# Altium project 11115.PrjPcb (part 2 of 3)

## Sheet 11115-4-USB-C Downstream 1-2.SchDoc
size Tabloid; CompanyName: Microchip Technology Inc.; Organization: Microchip Technology; Address1: 2355 West Chandler Blvd.; Address2: Chandler, AZ  85224; Address4: USA; SheetNumber: 4; SheetTotal: 6; SheetTitle: USB3.2 (Type-C) Downstream Ports 1 and 2
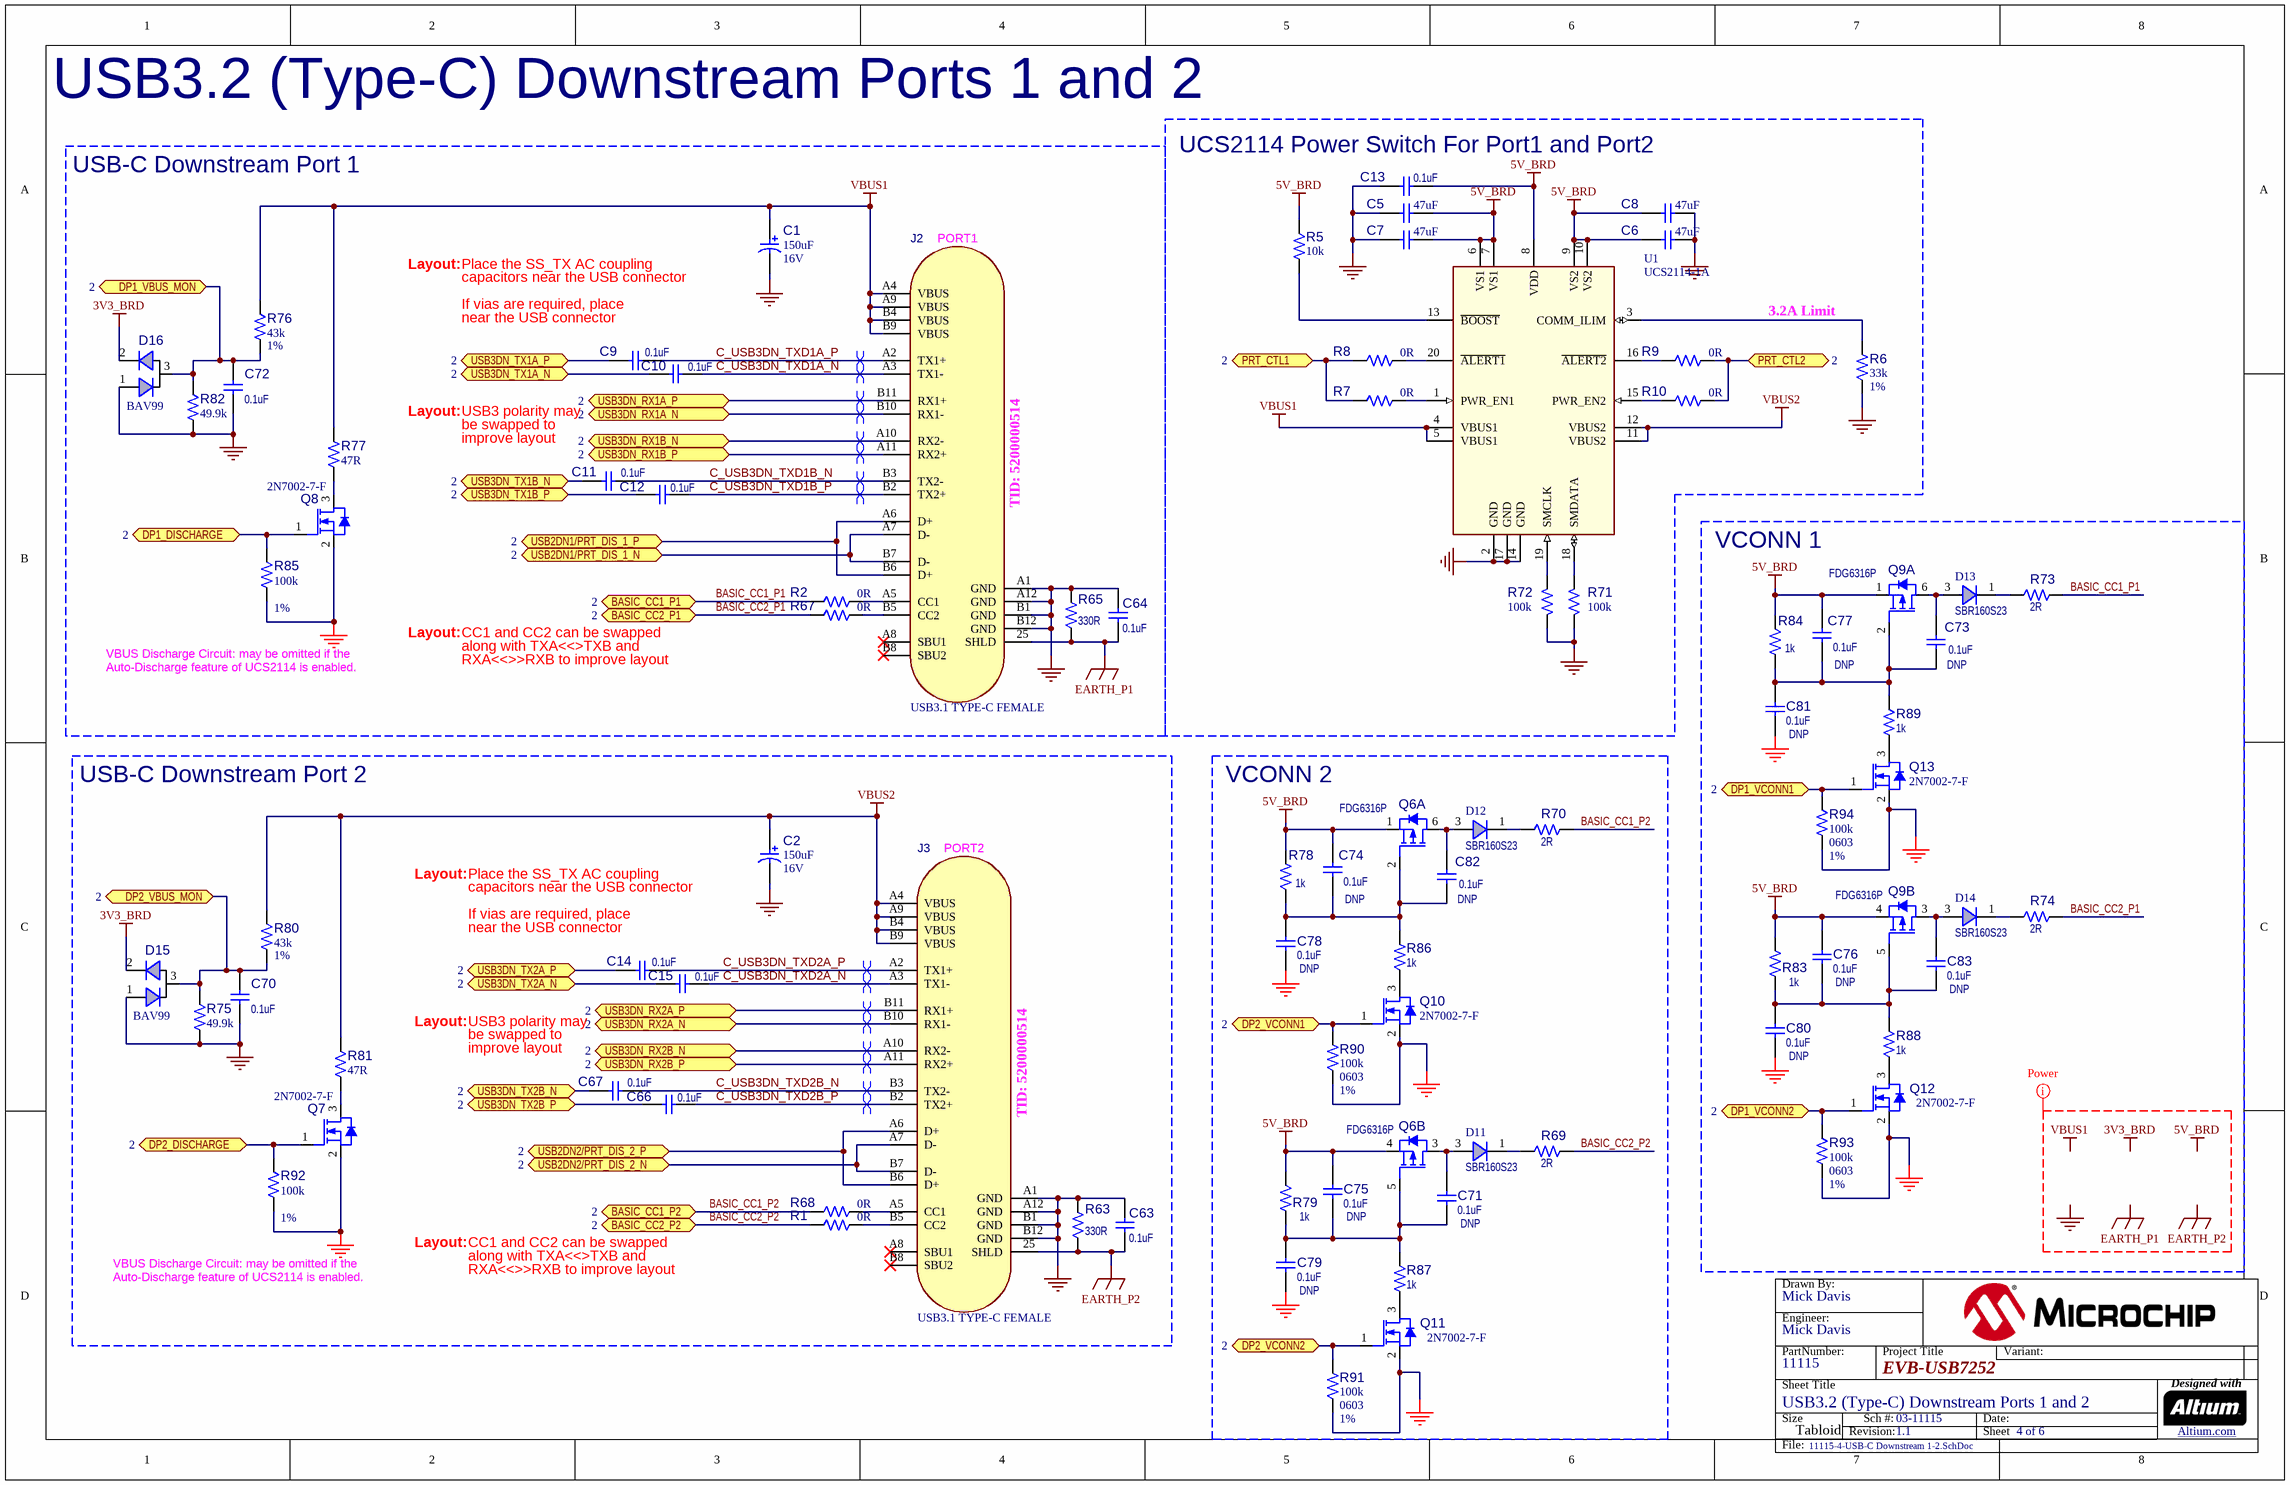
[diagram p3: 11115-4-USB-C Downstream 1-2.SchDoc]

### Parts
(Parts that share a designator on the sheet are numbered #1, #2 ... from top to bottom, then left to right.)
?#4  (no value)  (graphical)
C1  value 150uF  Voltage: 16V  [CAP_AL_D8]  (hidden comment: Capacitor POL)
C2  value 150uF  Voltage: 16V  [CAP_AL_D8]  (hidden comment: Capacitor POL)
C5  value 47uF  [CAP_C_0805]  (hidden comment: Capacitor NP)
C6  value 47uF  [CAP_C_0805]  (hidden comment: Capacitor NP)
C7  value 47uF  [CAP_C_0805]  (hidden comment: Capacitor NP)
C8  value 47uF  [CAP_C_0805]  (hidden comment: Capacitor NP)
C9  value 0.1uF  [CAP_C_0402]  (hidden comment: Capacitor NP)
C10  value 0.1uF  [CAP_C_0402]  (hidden comment: Capacitor NP)
C11  value 0.1uF  [CAP_C_0402]  (hidden comment: Capacitor NP)
C12  value 0.1uF  [CAP_C_0402]  (hidden comment: Capacitor NP)
C13  value 0.1uF  [CAP_C_0402]  (hidden comment: Capacitor NP)
C14  value 0.1uF  [CAP_C_0402]  (hidden comment: Capacitor NP)
C15  value 0.1uF  [CAP_C_0402]  (hidden comment: Capacitor NP)
C63  value 0.1uF  [CAP_C_0402]  (hidden comment: Capacitor NP)
C64  value 0.1uF  [CAP_C_0402]  (hidden comment: Capacitor NP)
C66  value 0.1uF  [CAP_C_0402]  (hidden comment: Capacitor NP)
C67  value 0.1uF  [CAP_C_0402]  (hidden comment: Capacitor NP)
C70  value 0.1uF  [CAP_C_0402]  (hidden comment: Capacitor NP)
C71  value 0.1uF  Populated: DNP  [CAP_C_0402]  (hidden comment: Capacitor NP)
C72  value 0.1uF  [CAP_C_0402]  (hidden comment: Capacitor NP)
C73  value 0.1uF  Populated: DNP  [CAP_C_0402]  (hidden comment: Capacitor NP)
C74  value 0.1uF  Populated: DNP  [CAP_C_0402]  (hidden comment: Capacitor NP)
C75  value 0.1uF  Populated: DNP  [CAP_C_0402]  (hidden comment: Capacitor NP)
C76  value 0.1uF  Populated: DNP  [CAP_C_0402]  (hidden comment: Capacitor NP)
C77  value 0.1uF  Populated: DNP  [CAP_C_0402]  (hidden comment: Capacitor NP)
C78  value 0.1uF  Populated: DNP  [CAP_C_0402]  (hidden comment: Capacitor NP)
C79  value 0.1uF  Populated: DNP  [CAP_C_0402]  (hidden comment: Capacitor NP)
C80  value 0.1uF  Populated: DNP  [CAP_C_0402]  (hidden comment: Capacitor NP)
C81  value 0.1uF  Populated: DNP  [CAP_C_0402]  (hidden comment: Capacitor NP)
C82  value 0.1uF  Populated: DNP  [CAP_C_0402]  (hidden comment: Capacitor NP)
C83  value 0.1uF  Populated: DNP  [CAP_C_0402]  (hidden comment: Capacitor NP)
D11  value SBR160S23  [SOT-23-3_REVERSED]  (hidden comment: Diode SBR160S23)
D12  value SBR160S23  [SOT-23-3_REVERSED]  (hidden comment: Diode SBR160S23)
D13  value SBR160S23  [SOT-23-3_REVERSED]  (hidden comment: Diode SBR160S23)
D14  value SBR160S23  [SOT-23-3_REVERSED]  (hidden comment: Diode SBR160S23)
D15  value BAV99  [SOT-23-3]  (hidden comment: Diode Dual AK)
D16  value BAV99  [SOT-23-3]  (hidden comment: Diode Dual AK)
J2  value USB3.1 TYPE-C FEMALE  [CON_USB3.1-C_RCPT_SMD_RA_ACP_12401610E4#2A]  (hidden comment: USBC_Receptacle_SMD_RA)
J3  value USB3.1 TYPE-C FEMALE  [CON_USB3.1-C_RCPT_SMD_RA_ACP_12401610E4#2A]  (hidden comment: USBC_Receptacle_SMD_RA)
Q6  value FDG6316P  [SC-88-6]  (hidden comment: Transistor MOS-P+P Dual SGDSGD)  (parts A,B of 2)
Q7  value 2N7002-7-F  [SOT-23-3]
Q8  value 2N7002-7-F  [SOT-23-3]
Q9  value FDG6316P  [SC-88-6]  (hidden comment: Transistor MOS-P+P Dual SGDSGD)  (parts A,B of 2)
Q10  value 2N7002-7-F  [SOT-23-3]
Q11  value 2N7002-7-F  [SOT-23-3]
Q12  value 2N7002-7-F  [SOT-23-3]
Q13  value 2N7002-7-F  [SOT-23-3]
R1  0R  [RES_C_0603]
R2  0R  [RES_C_0603]
R5  value 10k  [RES_C_0603]  (hidden comment: Resistor)
R6  value 33k  Tolerance: 1%  [RES_C_0603]  (hidden comment: Resistor)
R7  value 0R  [RES_C_0603]  (hidden comment: Resistor)
R8  value 0R  [RES_C_0603]  (hidden comment: Resistor)
R9  value 0R  [RES_C_0603]  (hidden comment: Resistor)
R10  value 0R  [RES_C_0603]  (hidden comment: Resistor)
R63  value 330R  [RES_C_0603]  (hidden comment: Resistor)
R65  value 330R  [RES_C_0603]  (hidden comment: Resistor)
R67  0R  [RES_C_0603]
R68  0R  [RES_C_0603]
R69  value 2R  [RES_C_0603]  (hidden comment: Resistor)
R70  value 2R  [RES_C_0603]  (hidden comment: Resistor)
R71  100k  [RES_C_0603]
R72  100k  [RES_C_0603]
R73  value 2R  [RES_C_0603]  (hidden comment: Resistor)
R74  value 2R  [RES_C_0603]  (hidden comment: Resistor)
R75  value 49.9k  [RES_C_0603]  (hidden comment: Resistor)
R76  value 43k  Tolerance: 1%  [RES_C_0603]  (hidden comment: Resistor)
R77  value 47R  [RES_C_0603]  (hidden comment: Resistor)
R78  value 1k  [RES_C_0603]  (hidden comment: Resistor)
R79  value 1k  [RES_C_0603]  (hidden comment: Resistor)
R80  value 43k  Tolerance: 1%  [RES_C_0603]  (hidden comment: Resistor)
R81  value 47R  [RES_C_0603]  (hidden comment: Resistor)
R82  value 49.9k  [RES_C_0603]  (hidden comment: Resistor)
R83  value 1k  [RES_C_0603]  (hidden comment: Resistor)
R84  value 1k  [RES_C_0603]  (hidden comment: Resistor)
R85  value 100k  Tolerance: 1%  [RES_C_0603]
R86  value 1k  [RES_C_0603]  (hidden comment: Resistor)
R87  value 1k  [RES_C_0603]  (hidden comment: Resistor)
R88  value 1k  [RES_C_0603]  (hidden comment: Resistor)
R89  value 1k  [RES_C_0603]  (hidden comment: Resistor)
R90  value 100k  Package: 0603  Tolerance: 1%  [RES_C_0603]
R91  value 100k  Package: 0603  Tolerance: 1%  [RES_C_0603]
R92  value 100k  Tolerance: 1%  [RES_C_0603]
R93  value 100k  Package: 0603  Tolerance: 1%  [RES_C_0603]
R94  value 100k  Package: 0603  Tolerance: 1%  [RES_C_0603]
U1  value UCS2114-1A  [QFN-20_3X3_P0.5_EP0_UCS2114]  (hidden comment: UCS2114 VQFN-20)

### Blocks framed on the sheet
USB-C Downstream Port 1: C1 C9-C12 C64 C72 D16 J2 Q8 R2 R65 R67 R76 R77 R82 R85
UCS2114 Power Switch For Port1 and Port2: C5-C8 C13 R5-R10 R71 R72 U1
VCONN 1: C73 C76 C77 C80 C81 C83 D13 D14 Q9 Q12 Q13 R73 R74 R83 R84 R88 R89 R93 R94
USB-C Downstream Port 2: C2 C14 C15 C63 C66 C67 C70 D15 J3 Q7 R1 R63 R68 R75 R80 R81 R92
VCONN 2: C71 C74 C75 C78 C79 C82 D11 D12 Q6 Q10 Q11 R69 R70 R78 R79 R86 R87 R90 R91

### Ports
BASIC_CC1_P1 (bidir, see 2), BASIC_CC1_P2 (bidir, see 2), BASIC_CC2_P1 (bidir, see 2), BASIC_CC2_P2 (bidir, see 2), DP1_DISCHARGE (bidir, see 2), DP1_VBUS_MON (bidir, see 2), DP1_VCONN1 (bidir, see 2), DP1_VCONN2 (bidir, see 2), DP2_DISCHARGE (bidir, see 2), DP2_VBUS_MON (bidir, see 2), DP2_VCONN1 (bidir, see 2), DP2_VCONN2 (bidir, see 2), PRT_CTL1 (bidir, see 2), PRT_CTL2 (bidir, see 2), USB2DN1/PRT_DIS_1_N (bidir, see 2), USB2DN1/PRT_DIS_1_P (bidir, see 2), USB2DN2/PRT_DIS_2_N (bidir, see 2), USB2DN2/PRT_DIS_2_P (bidir, see 2), USB3DN_RX1A_N (bidir, see 2), USB3DN_RX1A_P (bidir, see 2), USB3DN_RX1B_N (bidir, see 2), USB3DN_RX1B_P (bidir, see 2), USB3DN_RX2A_N (bidir, see 2), USB3DN_RX2A_P (bidir, see 2), USB3DN_RX2B_N (bidir, see 2), USB3DN_RX2B_P (bidir, see 2), USB3DN_TX1A_N (bidir, see 2), USB3DN_TX1A_P (bidir, see 2), USB3DN_TX1B_N (bidir, see 2), USB3DN_TX1B_P (bidir, see 2), USB3DN_TX2A_N (bidir, see 2), USB3DN_TX2A_P (bidir, see 2), USB3DN_TX2B_N (bidir, see 2), USB3DN_TX2B_P (bidir, see 2)

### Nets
3V3_BRD: D15.2(K) D16.2(K)
5V_BRD: C5.2 C6.1 C7.2 C8.1 C13.2 C74.2 C75.2 C76.2 C77.2 Q6.1(S1) Q6.4(S2) Q9.1(S1) Q9.4(S2) R5.1 R78.2 R79.2 R83.2 R84.2 U1.6(VS1) U1.7(VS1) U1.8(VDD) U1.9(VS2) U1.10(VS2)
EARTH_P1: C64.2 J2.25(SHLD) R65.1
EARTH_P2: C63.2 J3.25(SHLD) R63.1
GND: C1.2 C2.2 C5.1 C6.2 C7.1 C8.2 C13.1 C63.1 C64.1 C70.2 C72.2 C78.1 C79.1 C80.1 C81.1 D15.1(A) D16.1(A) J2.A1(GND) J2.A12(GND) J2.B1(GND) J2.B12(GND) J3.A1(GND) J3.A12(GND) J3.B1(GND) J3.B12(GND) Q7.2(S) Q8.2(S) Q10.2(S) Q11.2(S) Q12.2(S) Q13.2(S) R6.1 R63.2 R65.2 R71.2 R72.2 R75.1 R82.1 R85.1 R90.1 R91.1 R92.1 R93.1 R94.1 U1.2(GND) U1.14(GND) U1.17(GND)
VBUS1: C1.1 J2.A4(VBUS) J2.A9(VBUS) J2.B4(VBUS) J2.B9(VBUS) R76.2 R77.2 U1.4(VBUS1) U1.5(VBUS1)
VBUS2: C2.1 J3.A4(VBUS) J3.A9(VBUS) J3.B4(VBUS) J3.B9(VBUS) R80.2 R81.2 U1.11(VBUS2) U1.12(VBUS2)
BASIC_CC1_P1: R2.1 R73.2 ; port BASIC_CC1_P1
BASIC_CC1_P2: R68.1 R70.2 ; port BASIC_CC1_P2
BASIC_CC2_P1: R67.1 R74.2 ; port BASIC_CC2_P1
BASIC_CC2_P2: R1.1 R69.2 ; port BASIC_CC2_P2
C_USB3DN_TXD1A_N: C10.2 J2.A3(TX1-)
C_USB3DN_TXD1A_P: C9.2 J2.A2(TX1+)
C_USB3DN_TXD1B_N: C11.2 J2.B3(TX2-)
C_USB3DN_TXD1B_P: C12.2 J2.B2(TX2+)
C_USB3DN_TXD2A_N: C15.2 J3.A3(TX1-)
C_USB3DN_TXD2A_P: C14.2 J3.A2(TX1+)
C_USB3DN_TXD2B_N: C67.2 J3.B3(TX2-)
C_USB3DN_TXD2B_P: C66.2 J3.B2(TX2+)
DP1_DISCHARGE: Q8.1(G) R85.2 ; port DP1_DISCHARGE
DP1_VBUS_MON: C72.1 D16.3(KA) R76.1 R82.2 ; port DP1_VBUS_MON
DP1_VCONN1: Q13.1(G) R94.2 ; port DP1_VCONN1
DP1_VCONN2: Q12.1(G) R93.2 ; port DP1_VCONN2
DP2_DISCHARGE: Q7.1(G) R92.2 ; port DP2_DISCHARGE
DP2_VBUS_MON: C70.1 D15.3(KA) R75.2 R80.1 ; port DP2_VBUS_MON
DP2_VCONN1: Q10.1(G) R90.2 ; port DP2_VCONN1
DP2_VCONN2: Q11.1(G) R91.2 ; port DP2_VCONN2
PRT_CTL1: R7.1 R8.1 ; port PRT_CTL1
PRT_CTL2: R9.2 R10.2 ; port PRT_CTL2
USB2DN1/PRT_DIS_1_N: J2.A7(D-) J2.B7(D-) ; port USB2DN1/PRT_DIS_1_N
USB2DN1/PRT_DIS_1_P: J2.A6(D+) J2.B6(D+) ; port USB2DN1/PRT_DIS_1_P
USB2DN2/PRT_DIS_2_N: J3.A7(D-) J3.B7(D-) ; port USB2DN2/PRT_DIS_2_N
USB2DN2/PRT_DIS_2_P: J3.A6(D+) J3.B6(D+) ; port USB2DN2/PRT_DIS_2_P
USB3DN_RX1A_N: J2.B10(RX1-) ; port USB3DN_RX1A_N
USB3DN_RX1A_P: J2.B11(RX1+) ; port USB3DN_RX1A_P
USB3DN_RX1B_N: J2.A10(RX2-) ; port USB3DN_RX1B_N
USB3DN_RX1B_P: J2.A11(RX2+) ; port USB3DN_RX1B_P
USB3DN_RX2A_N: J3.B10(RX1-) ; port USB3DN_RX2A_N
USB3DN_RX2A_P: J3.B11(RX1+) ; port USB3DN_RX2A_P
USB3DN_RX2B_N: J3.A10(RX2-) ; port USB3DN_RX2B_N
USB3DN_RX2B_P: J3.A11(RX2+) ; port USB3DN_RX2B_P
USB3DN_TX1A_N: C10.1 ; port USB3DN_TX1A_N
USB3DN_TX1A_P: C9.1 ; port USB3DN_TX1A_P
USB3DN_TX1B_N: C11.1 ; port USB3DN_TX1B_N
USB3DN_TX1B_P: C12.1 ; port USB3DN_TX1B_P
USB3DN_TX2A_N: C15.1 ; port USB3DN_TX2A_N
USB3DN_TX2A_P: C14.1 ; port USB3DN_TX2A_P
USB3DN_TX2B_N: C67.1 ; port USB3DN_TX2B_N
USB3DN_TX2B_P: C66.1 ; port USB3DN_TX2B_P
NetC71_1: C71.1 C75.1 C79.2 Q6.5(G2) R79.1 R87.2
NetC71_2: C71.2 D11.3(A3) Q6.3(D2)
NetC73_1: C73.1 C77.1 C81.2 Q9.2(G1) R84.1 R89.2
NetC73_2: C73.2 D13.3(A3) Q9.6(D1)
NetC74_1: C74.1 C78.2 C82.1 Q6.2(G1) R78.1 R86.2
NetC76_1: C76.1 C80.2 C83.1 Q9.5(G2) R83.1 R88.2
NetC82_2: C82.2 D12.3(A3) Q6.6(D1)
NetC83_2: C83.2 D14.3(A3) Q9.3(D2)
NetD11_1: D11.1(K2) R69.1
NetD12_1: D12.1(K2) R70.1
NetD13_1: D13.1(K2) R73.1
NetD14_1: D14.1(K2) R74.1
NetJ2_A5: J2.A5(CC1) R2.2
NetJ2_B5: J2.B5(CC2) R67.2
NetJ3_A5: J3.A5(CC1) R68.2
NetJ3_B5: J3.B5(CC2) R1.2
NetQ7_3: Q7.3(D) R81.1
NetQ8_3: Q8.3(D) R77.1
NetQ10_3: Q10.3(D) R86.1
NetQ11_3: Q11.3(D) R87.1
NetQ12_3: Q12.3(D) R88.1
NetQ13_3: Q13.3(D) R89.1
NetR5_2: R5.2 U1.13(~{BOOST})
NetR6_2: R6.2 U1.3(COMM_ILIM)
NetR7_2: R7.2 U1.1(PWR_EN1)
NetR8_2: R8.2 U1.20(~{ALERT1})
NetR9_1: R9.1 U1.16(~{ALERT2})
NetR10_1: R10.1 U1.15(PWR_EN2)
NetR71_1: R71.1 U1.18(SMDATA)
NetR72_1: R72.1 U1.19(SMCLK)

Not connected (* = marked no-connect by the designer): J2 A8(SBU1)* B8(SBU2)*; J3 A8(SBU1)* B8(SBU2)*

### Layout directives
differential pair; net class USB3.: C_USB3DN_TXD1A_N, C_USB3DN_TXD1A_P, C_USB3DN_TXD1B_N, C_USB3DN_TXD1B_P, C_USB3DN_TXD2A_N, C_USB3DN_TXD2A_P, C_USB3DN_TXD2B_N, C_USB3DN_TXD2B_P, USB3DN_RX1A_N, USB3DN_RX1A_P, USB3DN_RX1B_N, USB3DN_RX1B_P, USB3DN_RX2A_N, USB3DN_RX2A_P, USB3DN_RX2B_N, USB3DN_RX2B_P
net class Power: 3V3_BRD, 5V_BRD, EARTH_P1, EARTH_P2, GND, VBUS1

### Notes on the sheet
- USB3.2 (Type-C) Downstream Ports 1 and 2
- Layout:
- Place the SS_TX AC coupling
- capacitors near the USB connector
- (near J2) PORT1
- If vias are required, place
- (near C9) near the USB connector
- (near R9) 3.2A Limit
- USB3 polarity may
- be swapped to
- (near C11) improve layout
- (near J2) TID: 5200000514
- VBUS Discharge Circuit: may be omitted if the
- Auto-Discharge feature of UCS2114 is enabled.
- CC1 and CC2 can be swapped
- along with TXA<<>TXB and
- RXA<<>>RXB to improve layout
- (near J3) PORT2
- (near C14) near the USB connector
- (near C67) improve layout
- (near J3) TID: 5200000514
- Labels drawn without touching a wire or pin: 3V3_BRD, 5V_BRD, EARTH_P1, EARTH_P2, GND, VBUS1

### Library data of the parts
?#4 = Title Block Tabloid
C1 C2 = CAP1298: Capacitor; Manufacturer 1: Panasonic Electronic Components; Manufacturer Part Number 1: EEE-FPC151XAP; Description_: CAP ALU 150uF 16V 20% SMD D8; Dev Tools Status: Production; Tolerance: 20%; ESR: 0.16R; Type: Aluminum; Owner: Stephen Humberd; Populated: YES
C5-C8 = CAP0646: Capacitor; Manufacturer 1: Taiyo Yuden; Manufacturer Part Number 1: JMK212BJ476MG-T; Description_: CAP CER 47uF 6.3V 20% X5R SMD 0805; Dev Tools Status: Production; Tolerance: 20%; Temperature Coeffcient: X5R; Type: Ceramic; Populated: Yes; Voltage: 6.3V
C9-C15 C63 C64 C66 C67 C70 C72 = CAP1337: Capacitor; Manufacturer 1: TDK Corporation; Manufacturer Part Number 1: CGA2B3X7R1V104K050BB; Voltage: 35V; Description_: CAP CER 0.1uF 35V 10% X7R SMD 0402; Dev Tools Status: Design; Tolerance: 10%; Temperature Coeffcient: X7R; Type: Ceramic; Owner: Sam Charles; Populated: YES
C71 C73-C83 = CAP1337: Capacitor; Manufacturer 1: TDK Corporation; Manufacturer Part Number 1: CGA2B3X7R1V104K050BB; Voltage: 35V; Description_: CAP CER 0.1uF 35V 10% X7R SMD 0402; Dev Tools Status: Design; Tolerance: 10%; Temperature Coeffcient: X7R; Type: Ceramic; Owner: Sam Charles
D11-D14 = DIODE1156: Manufacturer 1: Diodes Incorporated; Manufacturer Part Number 1: SBR160S23-7; Description_: DIO SBAR SBR160S23-7 SBR 530mV 900mA 60V SMD SOT23-3; Dev Tools Status: Production; Type: Super Barrier; Forward Current: 900mA; Reverse Current: 100µA @ 45V; Reverse Voltage: 60V; Owner: Sam Charles; Populated: YES
D15 D16 = DIODE0073: Manufacturer 1: Fairchild; Description_: DIO RECTARR BAV99 1.25V 200mA 70V SOT-23-3; Type: Rectifier Array; Forward Current: 200mA; Power: 350mW; Reverse Current: 2.5uA; Reverse Voltage: 70V; Populated: YES; Dev Tools Status: Production
J2 J3 = CON1809: Manufacturer 1: Amphenol Commercial Products; Manufacturer Part Number 1: 12401610E4#2A; Description_: CON USB3.1 TID TYPE-C Female SMD R/A; Dev Tools Status: Design; Owner: Jennifer Hancock; Current: 5A; Populated: YES
Q6 Q9 = TRA1232: Transistor MOS Dual P+P SGDSGD; Manufacturer 1: ON Semiconductor; Description_: TRANS FET DUAL P+P FDG6316P 12V 0.7A 0.270R 0.3R SC-88; Dev Tools Status: Design; Type: FET; Current: 300mA; Drain to Source Voltage: 12V; Gate to Source Voltage: 1.5V; Power: 0.3W; Owner: Sam Charles; Populated: YES
Q7 Q8 Q10-Q13 = TRA1102: Transistor MOS; Manufacturer 1: Diodes Inc; Description_: TRANS FET N-CH 2N7002-7-F 60V 170mA 370mW SOT-23-3; Dev Tools Status: Production; Type: FET; Current: 170mA; Drain to Source Voltage: 60V; Gate to Source Voltage: 20V; Power: 370mW; Owner: Adrian M (M91404); Populated: YES
R1 R2 R67 R68 = RSMT0001: Resistor; Manufacturer 1: NIC Components; Manufacturer Part Number 1: NRC06Z0TRF; Description_: RES TKF 0R 1/10W SMD 0603; Power: 1/10W; Populated: Yes
R5 = RSMT0625: Manufacturer 1: ROHM; Manufacturer Part Number 1: MCR03EZPFX1002; Tolerance: 1%; Description_: RES TKF 10k 1% 1/10W SMD 0603; Voltage: 75V; Temperature Coeffcient: 100ppm/C; Power: 1/10W; Populated: Yes; Dev Tools Status: Production
R6 = RES1169: Manufacturer 1: Panasonic; Manufacturer Part Number 1: ERJ-3EKF3302V; Description_: RES TKF 33k 1% 1/10W SMD 0603; Dev Tools Status: Production; Voltage: 75V; Temperature Coeffcient: 100ppm/C; Power: 1/10W; Owner: Bogdan P (M91398); Populated: Yes
R7-R10 = RSMT0001: Manufacturer 1: Panasonic; Manufacturer Part Number 1: ERJ-3GSY0R00V; Description_: RES TKF 0R 1/10W SMD 0603; Power: 1/10W; Populated: Yes; Dev Tools Status: Production
R63 R65 = RSMT0626: Manufacturer 1: Panasonic; Manufacturer Part Number 1: ERJ-3EKF3300V; Tolerance: 1%; Description_: RES TKF 330R 1% 1/10W SMD 0603; Dev Tools Status: Production; Voltage: 75V; Temperature Coeffcient: 100ppm/C; Power: 1/10W; Populated: Yes
R69 R70 R73 R74 = RES1566: Manufacturer 1: Vishay Dale; Manufacturer Part Number 1: CRCW06032R00FKEAHP; Tolerance: 1%; Description_: RES TKF 2R 1% 1/4W SMD 0603; Dev Tools Status: Production; Voltage: 75V; Temperature Coeffcient: 100ppm/C; Power: 1/10W; Owner: Tad Ahlvers; Populated: YES
R71 R72 = RSMT0215: Resistor; Manufacturer 1: Panasonic; Manufacturer Part Number 1: ERJ-3EKF1003V; Description_: RES TKF 100k 1% 1/10W SMD 0603; Voltage: 75V; Temperature Coeffcient: 100ppm/C; Power: 1/10W; Populated: Yes
R75 R82 = RSMT0383: Manufacturer 1: Panasonic; Manufacturer Part Number 1: ERJ-3EKF4992V; Tolerance: 1%; Description_: RES TKF 49.9k 1% 1/10W SMD 0603; Dev Tools Status: Production; Voltage: 75V; Temperature Coeffcient: 100ppm/C; Power: 1/10W; Populated: Yes
R76 R80 = RSMT0665: Manufacturer 1: Yageo; Manufacturer Part Number 1: 9C06031A4302FKHFT; Description_: RES TKF 43k 1% 1/10W SMD 0603; Dev Tools Status: Production; Voltage: 50V; Temperature Coeffcient: 100ppm/C; Power: 1/10W; Populated: Yes
R77 R81 = RSMT0703: Manufacturer 1: ROHM; Manufacturer Part Number 1: MCR03EZPFX47R0; Tolerance: 1%; Description_: RES TKF 47R 1% 1/10W SMD 0603; Dev Tools Status: Production; Voltage: 50V; Temperature Coeffcient: 100ppm/C; Power: 1/10W; Populated: Yes
R78 R79 R83 R84 R86-R89 = RSMT0138: Manufacturer 1: Panasonic; Manufacturer Part Number 1: ERJ-3EKF1001V; Tolerance: 1%; Description_: RES TKF 1k 1% 1/10W SMD 0603; Dev Tools Status: Production; Voltage: 75V; Temperature Coeffcient: 100ppm/C; Power: 1/10W; Populated: Yes
R85 R90-R94 = RSMT0215: Resistor; Manufacturer 1: Panasonic; Manufacturer Part Number 1: ERJ-3EKF1003V; Description_: RES TKF 100k 1% 1/10W SMD 0603; Voltage: 75V; Temperature Coeffcient: 100ppm/C; Power: 1/10W; Populated: Yes; Dev Tools Status: Production
U1 = MIC8861: UCS2114 Dual USB port power; Manufacturer 1: Microchip Technology; Manufacturer Part Number 1: UCS2114-1A-V/LX; Description_: MCHP INTERFACE USB Pwr Controller w/Auto Dischg UCS2114 QFN-20; Dev Tools Status: Design; Owner: Sam Charles; Populated: YES

## Sheet 11115-5-USB-A Downstream 3-4.SchDoc
size Tabloid; CompanyName: Microchip Technology Inc.; Organization: Microchip Technology; Address1: 2355 West Chandler Blvd.; Address2: Chandler, AZ  85224; Address4: USA; SheetNumber: 5; SheetTotal: 6; SheetTitle: USB (Type-A) Downstream Ports 3-4
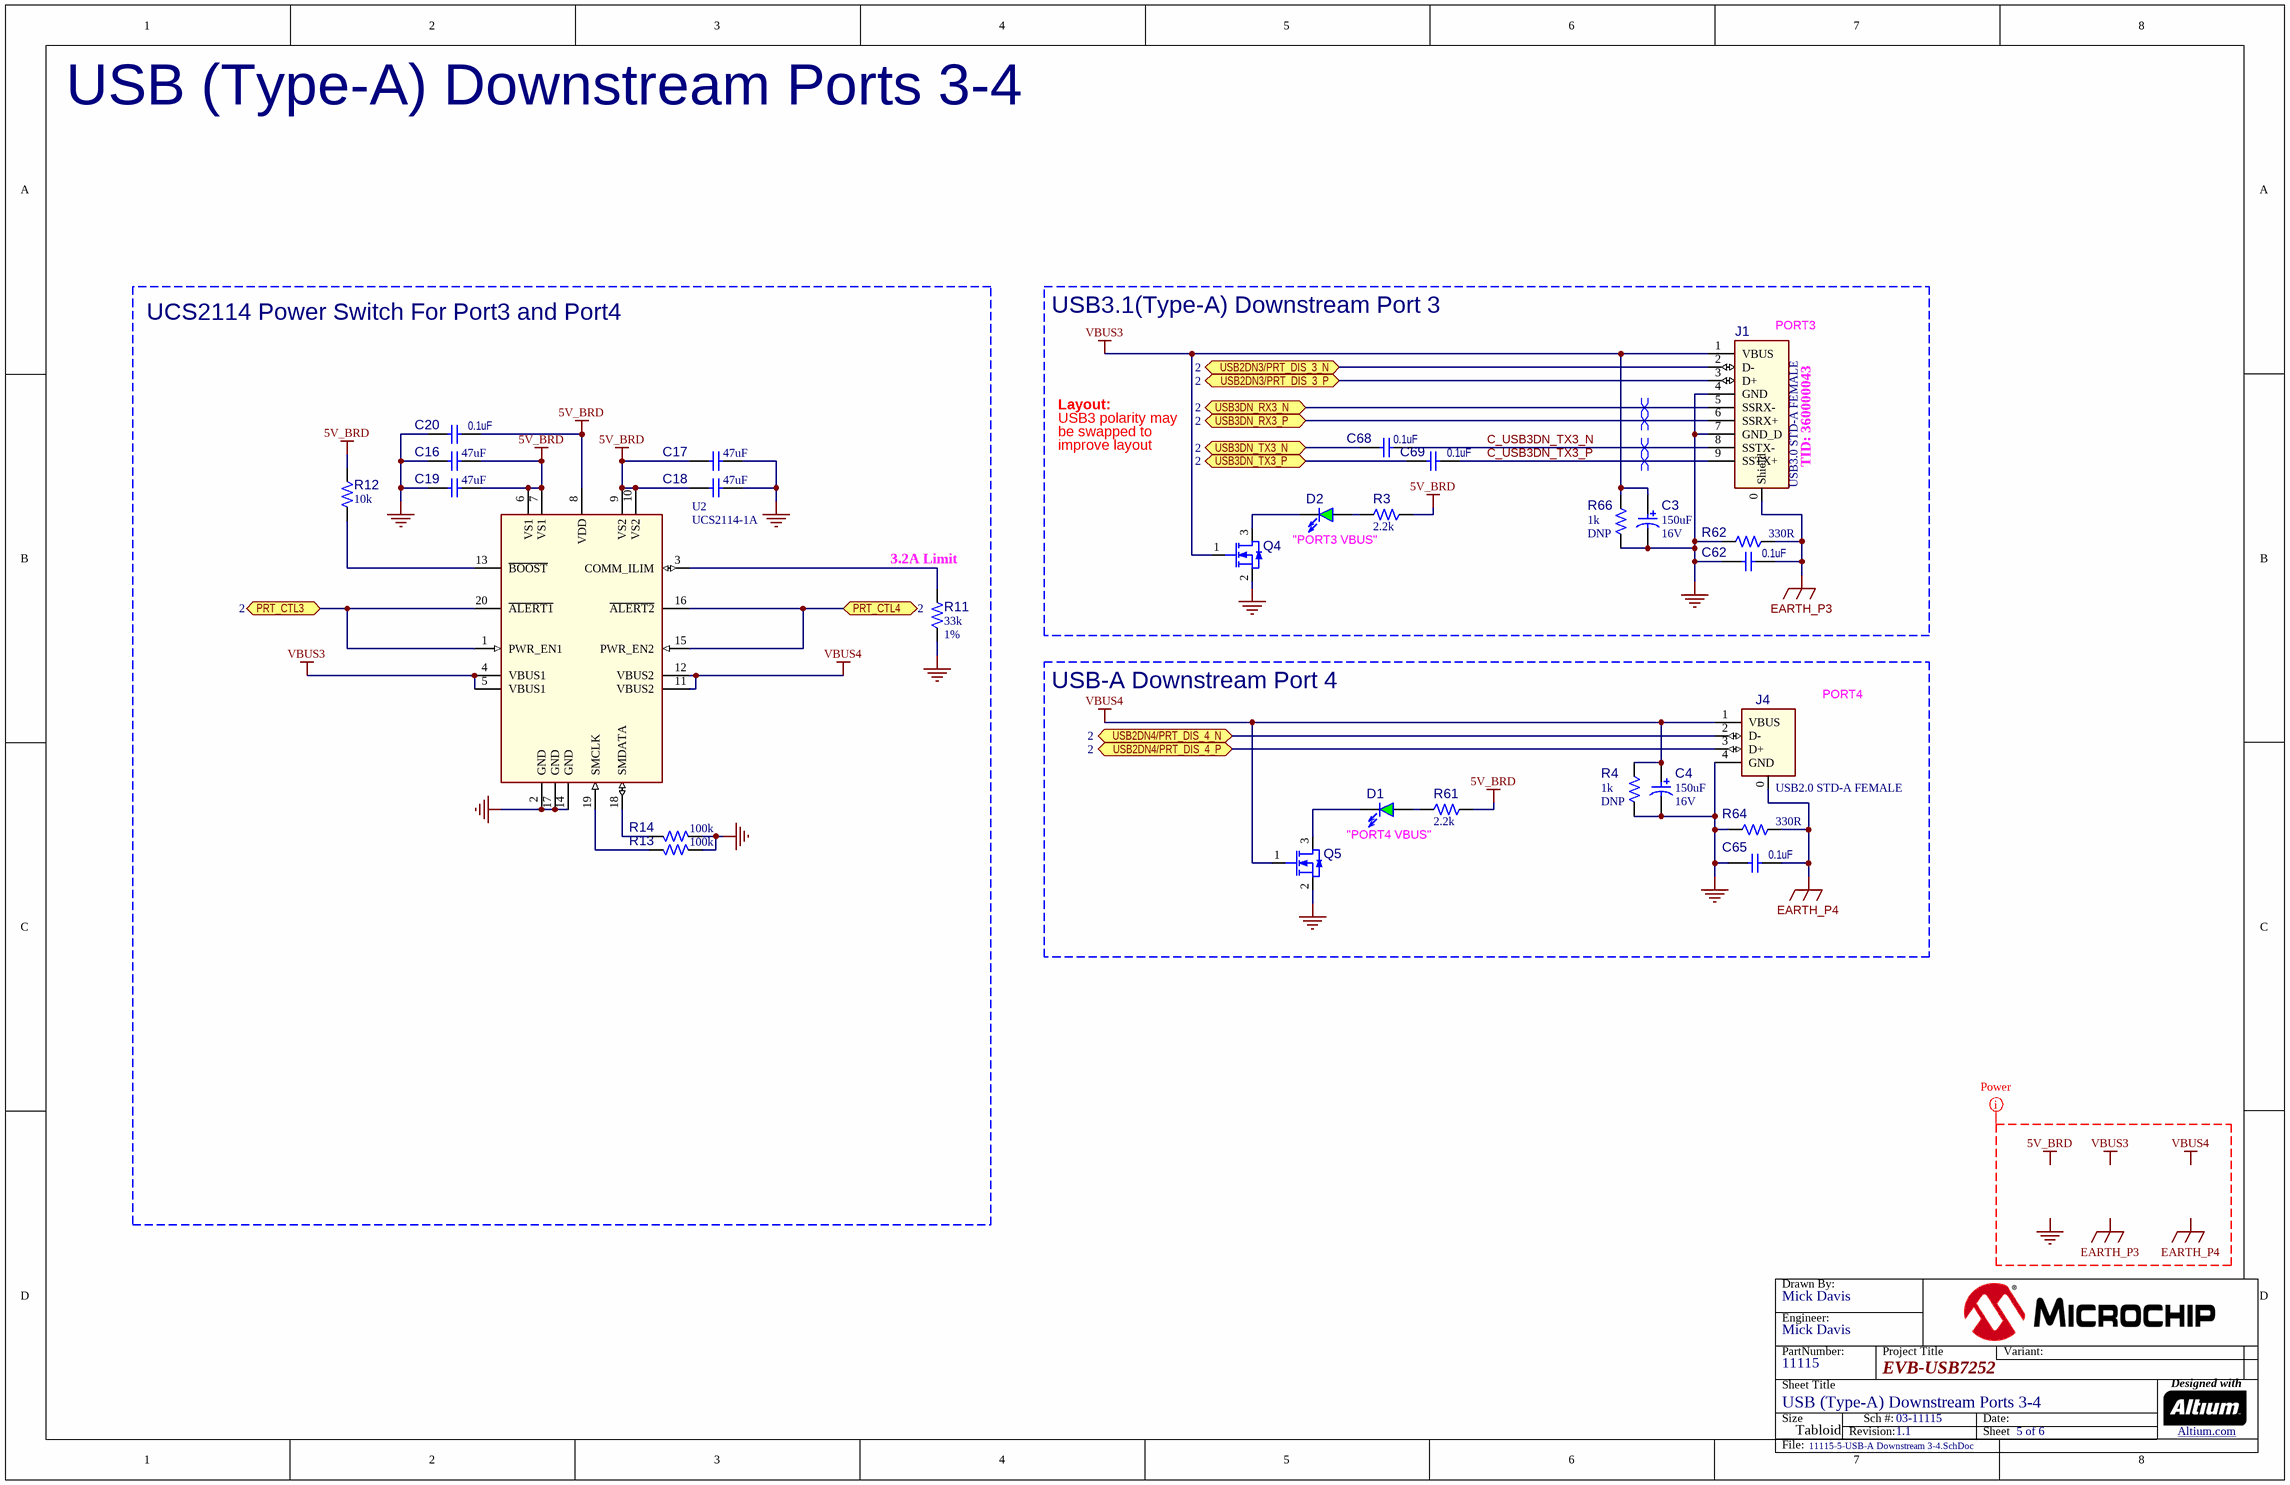
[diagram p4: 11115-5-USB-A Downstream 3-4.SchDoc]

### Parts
(Parts that share a designator on the sheet are numbered #1, #2 ... from top to bottom, then left to right.)
?#5  (no value)  (graphical)
C3  value 150uF  Voltage: 16V  [CAP_AL_D8]  (hidden comment: Capacitor POL)
C4  value 150uF  Voltage: 16V  [CAP_AL_D8]  (hidden comment: Capacitor POL)
C16  value 47uF  [CAP_C_0805]  (hidden comment: Capacitor NP)
C17  value 47uF  [CAP_C_0805]  (hidden comment: Capacitor NP)
C18  value 47uF  [CAP_C_0805]  (hidden comment: Capacitor NP)
C19  value 47uF  [CAP_C_0805]  (hidden comment: Capacitor NP)
C20  value 0.1uF  [CAP_C_0402]  (hidden comment: Capacitor NP)
C62  value 0.1uF  [CAP_C_0402]  (hidden comment: Capacitor NP)
C65  value 0.1uF  [CAP_C_0402]  (hidden comment: Capacitor NP)
C68  value 0.1uF  [CAP_C_0402]  (hidden comment: Capacitor NP)
C69  value 0.1uF  [CAP_C_0402]  (hidden comment: Capacitor NP)
D1  LED_green  [LED_0603_GREEN]  (value not drawn)
D2  LED_green  [LED_0603_GREEN]  (value not drawn)
J1  value USB3.0 STD-A FEMALE  [CON_USB3.0-A_RCPT_TH_RA_WE_692121030100]  (hidden comment: CON USB3.0 A-B)
J4  value USB2.0 STD-A FEMALE  [CON_USB2.0-A_TH_RA_FCI_87520-0010BLF]  (hidden comment: CON USB2.0 A-B)
Q4  Transistor MOS-N GSD  [SOT-23-3]  (value not drawn)
Q5  Transistor MOS-N GSD  [SOT-23-3]  (value not drawn)
R3  value 2.2k  [RES_C_0603]  (hidden comment: Resistor)
R4  value 1k  Populated: DNP  [RES_C_0603]  (hidden comment: Resistor)
R11  value 33k  Tolerance: 1%  [RES_C_0603]  (hidden comment: Resistor)
R12  value 10k  [RES_C_0603]  (hidden comment: Resistor)
R13  100k  [RES_C_0603]
R14  100k  [RES_C_0603]
R61  value 2.2k  [RES_C_0603]  (hidden comment: Resistor)
R62  value 330R  [RES_C_0603]  (hidden comment: Resistor)
R64  value 330R  [RES_C_0603]  (hidden comment: Resistor)
R66  value 1k  Populated: DNP  [RES_C_0603]  (hidden comment: Resistor)
U2  value UCS2114-1A  [QFN-20_3X3_P0.5_EP0_UCS2114]  (hidden comment: UCS2114 VQFN-20)

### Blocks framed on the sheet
UCS2114 Power Switch For Port3 and Port4: C16-C20 R11-R14 U2
USB3.1(Type-A) Downstream Port 3: C3 C62 C68 C69 D2 J1 Q4 R3 R62 R66
USB-A Downstream Port 4: C4 C65 D1 J4 Q5 R4 R61 R64

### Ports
PRT_CTL3 (bidir, see 2), PRT_CTL4 (bidir, see 2), USB2DN3/PRT_DIS_3_N (bidir, see 2), USB2DN3/PRT_DIS_3_P (bidir, see 2), USB2DN4/PRT_DIS_4_N (bidir, see 2), USB2DN4/PRT_DIS_4_P (bidir, see 2), USB3DN_RX3_N (bidir, see 2), USB3DN_RX3_P (bidir, see 2), USB3DN_TX3_N (bidir, see 2), USB3DN_TX3_P (bidir, see 2)

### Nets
5V_BRD: C16.2 C17.1 C18.1 C19.2 C20.2 R3.1 R12.1 R61.1 U2.6(VS1) U2.7(VS1) U2.8(VDD) U2.9(VS2) U2.10(VS2)
EARTH_P3: C62.2 J1.0(Shield) R62.2
EARTH_P4: C65.2 J4.0(SHLD) R64.2
GND: C3.2 C4.2 C16.1 C17.2 C18.2 C19.1 C20.1 C62.1 C65.1 J1.4(GND) J1.7(GND_D) J4.4(GND) Q4.2(S) Q5.2(S) R4.1 R11.1 R13.2 R14.2 R62.1 R64.1 R66.1 U2.2(GND) U2.14(GND) U2.17(GND)
VBUS3: C3.1 J1.1(VBUS) Q4.1(G) R66.2 U2.4(VBUS1) U2.5(VBUS1)
VBUS4: C4.1 J4.1(VBUS) Q5.1(G) R4.2 U2.11(VBUS2) U2.12(VBUS2)
C_USB3DN_TX3_N: C68.2 J1.8(SSTX-)
C_USB3DN_TX3_P: C69.2 J1.9(SSTX+)
PRT_CTL3: U2.1(PWR_EN1) U2.20(~{ALERT1}) ; port PRT_CTL3
PRT_CTL4: U2.15(PWR_EN2) U2.16(~{ALERT2}) ; port PRT_CTL4
USB2DN3/PRT_DIS_3_N: J1.2(D-) ; port USB2DN3/PRT_DIS_3_N
USB2DN3/PRT_DIS_3_P: J1.3(D+) ; port USB2DN3/PRT_DIS_3_P
USB2DN4/PRT_DIS_4_N: J4.2(D-) ; port USB2DN4/PRT_DIS_4_N
USB2DN4/PRT_DIS_4_P: J4.3(D+) ; port USB2DN4/PRT_DIS_4_P
USB3DN_RX3_N: J1.5(SSRX-) ; port USB3DN_RX3_N
USB3DN_RX3_P: J1.6(SSRX+) ; port USB3DN_RX3_P
USB3DN_TX3_N: C68.1 ; port USB3DN_TX3_N
USB3DN_TX3_P: C69.1 ; port USB3DN_TX3_P
NetD1_1: D1.1(A) R61.2
NetD1_2: D1.2(K) Q5.3(D)
NetD2_1: D2.1(A) R3.2
NetD2_2: D2.2(K) Q4.3(D)
NetR11_2: R11.2 U2.3(COMM_ILIM)
NetR12_2: R12.2 U2.13(~{BOOST})
NetR13_1: R13.1 U2.19(SMCLK)
NetR14_1: R14.1 U2.18(SMDATA)

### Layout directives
net class Power: 5V_BRD, EARTH_P3, EARTH_P4, GND, VBUS3, VBUS4
differential pair; net class USB3.: C_USB3DN_TX3_N, C_USB3DN_TX3_P, USB3DN_RX3_N, USB3DN_RX3_P

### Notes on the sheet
- USB (Type-A) Downstream Ports 3-4
- (near J1) PORT3
- USB3 polarity may
- be swapped to
- Layout:
- improve layout
- (near J1) TID: 360000043
- 3.2A Limit
- "PORT3 VBUS"
- (near J4) PORT4
- "PORT4 VBUS"
- Labels drawn without touching a wire or pin: 5V_BRD, EARTH_P3, EARTH_P4, GND, VBUS3, VBUS4

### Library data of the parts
?#5 = Title Block Tabloid
C3 C4 = CAP1298: as C1 on sheet 11115-4-USB-C Downstream 1-2
C16-C19 = CAP0646: as C5 on sheet 11115-4-USB-C Downstream 1-2
C20 C62 C65 C68 C69 = CAP1337: as C9-C15 on sheet 11115-4-USB-C Downstream 1-2
D1 D2 = DIODE1155: LED; Manufacturer 1: Lite-On Inc; Manufacturer Part Number 1: LTST-C191KGKT; Value: GREEN; Description_: DIO LED GREEN 2V 30mA 35mcd Clear SMD 0603; Dev Tools Status: Production; Type: LED Single; Forward Current: 30mA; Power: 75mW; Reverse Voltage: 5V; Owner: Tad Ahlvers; Populated: YES
J1 = CON1254: Connector USB; Manufacturer 1: Wurth Electronics Inc; Manufacturer Part Number 1: 692121030100; Description_: CON USB3.0 STD-A FEMALE TH R/A; Dev Tools Status: Production; Owner: Bogdan Popescu; Voltage: 30V; Current: 1.8A; Populated: YES
J4 = CON0280: Connector USB; Manufacturer 1: TE Connectivity AMP Connectors; Manufacturer Part Number 1: 292303-1; Description_: CON USB2.0 STD-A FEMALE TH R/A; Owner: Bogdan Popescu; Populated: YES; Dev Tools Status: Production
Q4 Q5 = TRA1102: Transistor MOS; Manufacturer 1: Diodes Inc; Value: 2N7002-7-F; Description_: TRANS FET N-CH 2N7002-7-F 60V 170mA 370mW SOT-23-3; Dev Tools Status: Production; Type: FET; Current: 170mA; Drain to Source Voltage: 60V; Gate to Source Voltage: 20V; Power: 370mW; Owner: Adrian M (M91404); Populated: YES
R3 R61 = RES1130: Manufacturer 1: Panasonic; Manufacturer Part Number 1: ERJ-3EKF2201V; Tolerance: 1%; Description_: RES TKF 2.2k 1% 1/10W SMD 0603; Voltage: 75V; Temperature Coeffcient: 100ppm/C; Power: 1/10W; Owner: Bogdan P (M91398); Populated: Yes
R4 R66 = RSMT0138: Manufacturer 1: Panasonic; Manufacturer Part Number 1: ERJ-3EKF1001V; Tolerance: 1%; Description_: RES TKF 1k 1% 1/10W SMD 0603; Voltage: 75V; Temperature Coeffcient: 100ppm/C; Power: 1/10W; Dev Tools Status: Production
R11 = RES1169: as R6 on sheet 11115-4-USB-C Downstream 1-2
R12 = RSMT0625: as R5 on sheet 11115-4-USB-C Downstream 1-2
R13 R14 = RSMT0215: as R71 on sheet 11115-4-USB-C Downstream 1-2
R62 R64 = RSMT0626: Manufacturer 1: Panasonic; Manufacturer Part Number 1: ERJ-3EKF3300V; Tolerance: 1%; Description_: RES TKF 330R 1% 1/10W SMD 0603; Voltage: 75V; Temperature Coeffcient: 100ppm/C; Power: 1/10W; Populated: Yes; Dev Tools Status: Production
U2 = MIC8861: as U1 on sheet 11115-4-USB-C Downstream 1-2

## Sheet 11115-6-Voltage_Regulators.SchDoc
size Tabloid; CompanyName: Microchip Technology Inc.; Organization: Microchip Technology; Address1: 2355 West Chandler Blvd.; Address2: Chandler, AZ  85224; Address4: USA; SheetNumber: 6; SheetTotal: 6; SheetTitle: Voltage Regulators, GP LEDs, LED Drivers
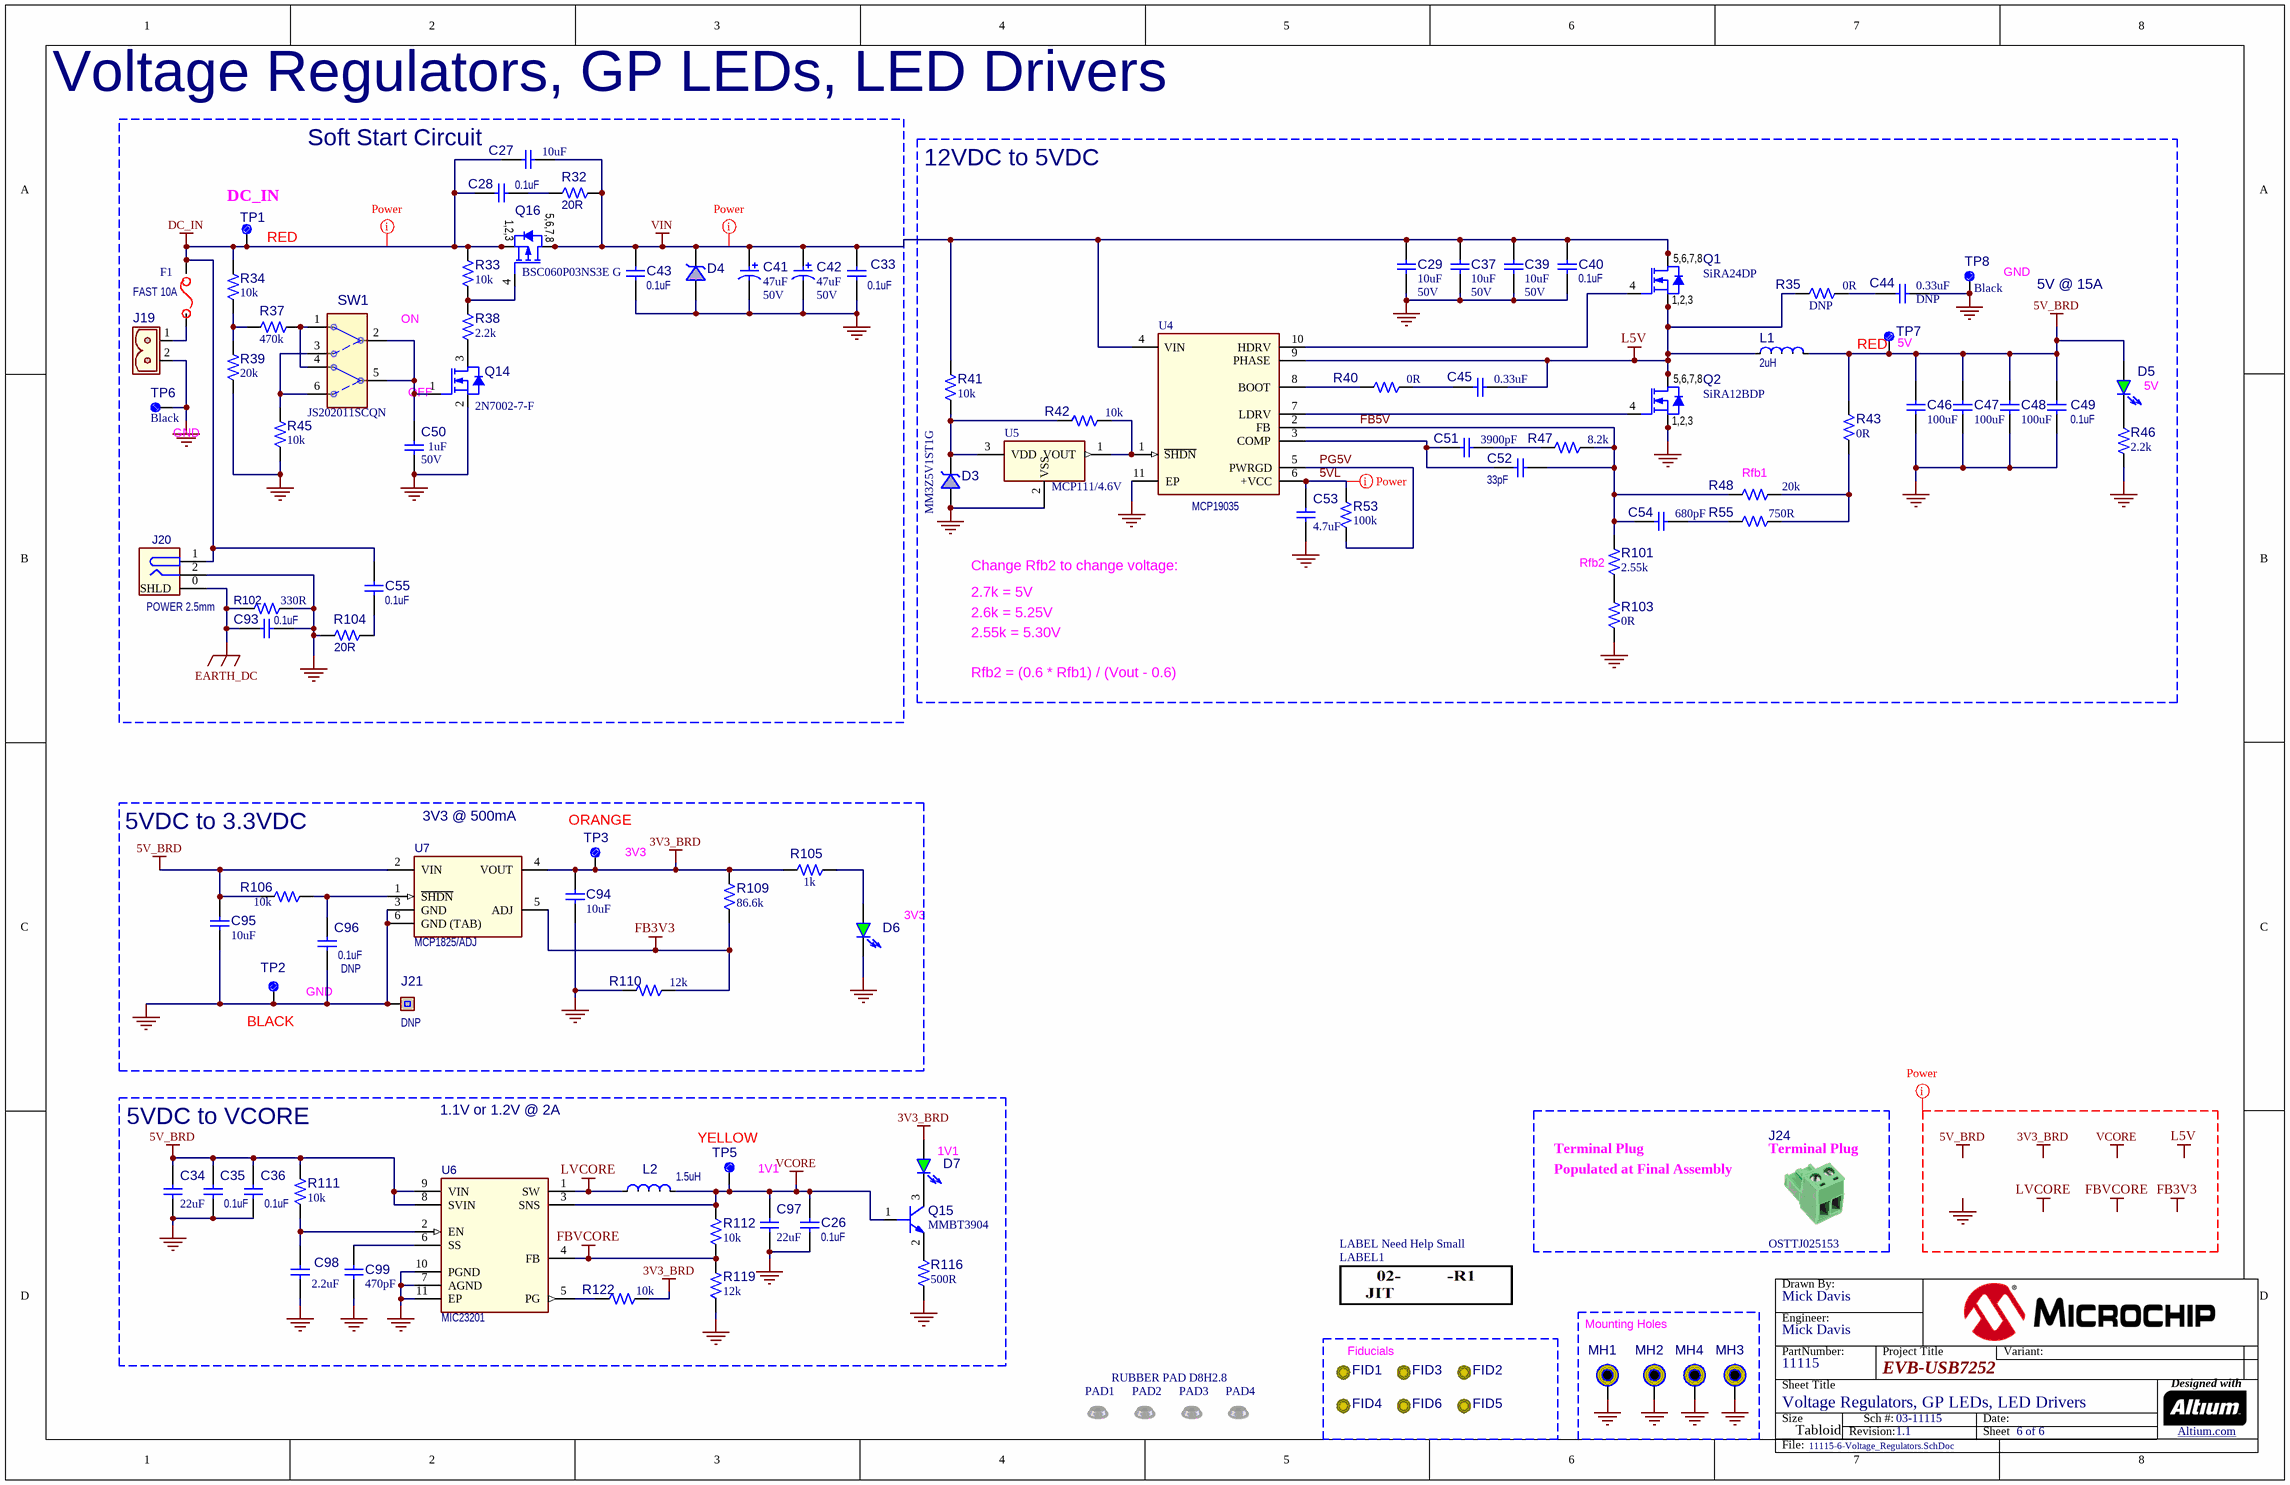
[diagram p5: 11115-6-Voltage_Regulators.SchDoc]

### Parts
(Parts that share a designator on the sheet are numbered #1, #2 ... from top to bottom, then left to right.)
?#6  (no value)  (graphical)
C26  value 0.1uF  [CAP_C_0402]  (hidden comment: Capacitor NP)
C27  value 10uF  [CAP_C_0805]  (hidden comment: Capacitor NP)
C28  value 0.1uF  [CAP_C_0402]  (hidden comment: Capacitor NP)
C29  value 10uF  Voltage: 50V  [CAP_C_1206]  (hidden comment: Capacitor NP)
C33  value 0.1uF  [CAP_C_0402]  (hidden comment: Capacitor NP)
C34  value 22uF  [CAP_C_1206]  (hidden comment: Capacitor NP)
C35  value 0.1uF  [CAP_C_0402]  (hidden comment: Capacitor NP)
C36  value 0.1uF  [CAP_C_0402]  (hidden comment: Capacitor NP)
C37  value 10uF  Voltage: 50V  [CAP_C_1206]  (hidden comment: Capacitor NP)
C39  value 10uF  Voltage: 50V  [CAP_C_1206]  (hidden comment: Capacitor NP)
C40  value 0.1uF  [CAP_C_0402]  (hidden comment: Capacitor NP)
C41  value 47uF  Voltage: 50V  [CAP_AL_F]  (hidden comment: Capacitor POL)
C42  value 47uF  Voltage: 50V  [CAP_AL_F]  (hidden comment: Capacitor POL)
C43  value 0.1uF  [CAP_C_0402]  (hidden comment: Capacitor NP)
C44  value 0.33uF  Populated: DNP  [CAP_C_0603]  (hidden comment: Capacitor NP)
C45  value 0.33uF  [CAP_C_0603]  (hidden comment: Capacitor NP)
C46  value 100uF  [CAP_C_1210]  (hidden comment: Capacitor NP)
C47  value 100uF  [CAP_C_1210]  (hidden comment: Capacitor NP)
C48  value 100uF  [CAP_C_1210]  (hidden comment: Capacitor NP)
C49  value 0.1uF  [CAP_C_0402]  (hidden comment: Capacitor NP)
C50  value 1uF  Voltage: 50V  [CAP_C_0603]  (hidden comment: Capacitor NP)
C51  value 3900pF  [CAP_C_0603]  (hidden comment: Capacitor NP)
C52  value 33pF  [CAP_C_0603]  (hidden comment: Capacitor NP)
C53  value 4.7uF  [CAP_C_0603]  (hidden comment: Capacitor NP)
C54  value 680pF  [CAP_C_0603]  (hidden comment: Capacitor NP)
C55  value 0.1uF  [CAP_C_0402]  (hidden comment: Capacitor NP)
C93  value 0.1uF  [CAP_C_0402]  (hidden comment: Capacitor NP)
C94  value 10uF  [CAP_C_0805]  (hidden comment: Capacitor NP)
C95  value 10uF  [CAP_C_0805]  (hidden comment: Capacitor NP)
C96  value 0.1uF  Populated: DNP  [CAP_C_0402]  (hidden comment: Capacitor NP)
C97  value 22uF  [CAP_C_1206]  (hidden comment: Capacitor NP)
C98  value 2.2uF  [CAP_C_0402]  (hidden comment: Capacitor NP)
C99  value 470pF  [CAP_C_0603]  (hidden comment: Capacitor NP)
D3  value MM3Z5V1ST1G  [SOD-323]  (hidden comment: Diode Zener)
D4  Diode TVS Unidirectional  [DO-214AC_SMA]  (value not drawn)
D5  LED_green  [LED_0603_GREEN]  (value not drawn)
D6  LED_green  [LED_0603_GREEN]  (value not drawn)
D7  LED_green  [LED_0603_GREEN]  (value not drawn)
F1  value FAST 10A  [FUSEHOLDER_LITTLEFUSE_155900]  (hidden comment: FUSE 2 pin)
FID1  FIDUCIAL  [FIDUCIAL]  (value not drawn)  (no BOM)
FID2  FIDUCIAL  [FIDUCIAL]  (value not drawn)  (no BOM)
FID3  FIDUCIAL  [FIDUCIAL]  (value not drawn)  (no BOM)
FID4  FIDUCIAL  [FIDUCIAL]  (value not drawn)  (no BOM)
FID5  FIDUCIAL  [FIDUCIAL]  (value not drawn)  (no BOM)
FID6  FIDUCIAL  [FIDUCIAL]  (value not drawn)  (no BOM)
J19  Header 1x2  [CON_TERMINAL_5.08_1x2_TH_RA_OST_OSTOQ025451]  (value not drawn)
J20  value POWER 2.5mm  [CON_JACK_POWER_TH_RA_CUI_PJ-063BH]  (hidden comment: CON JACK 2C SHLD)
J21  Populated: DNP  [HDR_M_2.54_1x1]  (hidden comment: Header 1x1)
J24  value OSTTJ025153  (hidden comment: CON TERMINAL 1X2 OSTTJ02)  (mechanical)
L1  value 2uH  [IND_WE_7443551200_L12.8W12.8H6.2]  (hidden comment: Inductor)
L2  value 1.5uH  [IND_MUR_LQH5B_L5W5H2]  (hidden comment: Inductor)
LABEL1  value LABEL Need Help Small  [LABEL_Need_Help_Small]  (hidden comment: LABEL_Need_Help_Small)
MH1  MTHOLE 4-40 120DL 220PAD  [MTHOLE_4-40]  (value not drawn)  (no BOM)
MH2  MTHOLE 4-40 120DL 220PAD  [MTHOLE_4-40]  (value not drawn)  (no BOM)
MH3  MTHOLE 4-40 120DL 220PAD  [MTHOLE_4-40]  (value not drawn)  (no BOM)
MH4  MTHOLE 4-40 120DL 220PAD  [MTHOLE_4-40]  (value not drawn)  (no BOM)
PAD1  value RUBBER PAD D8H2.8  [BUMP_3M_SJ5076_CYLINDRICAL_BLACK_D8H2.8]  (hidden comment: Rubber Pad Cylindrical Taper)  (mechanical)
PAD2  Rubber Pad Cylindrical Taper  [BUMP_3M_SJ5076_CYLINDRICAL_BLACK_D8H2.8]  (value not drawn)  (mechanical)
PAD3  Rubber Pad Cylindrical Taper  [BUMP_3M_SJ5076_CYLINDRICAL_BLACK_D8H2.8]  (value not drawn)  (mechanical)
PAD4  Rubber Pad Cylindrical Taper  [BUMP_3M_SJ5076_CYLINDRICAL_BLACK_D8H2.8]  (value not drawn)  (mechanical)
Q1  value SiRA24DP  [Power56-8_5x6]  (hidden comment: Transistor MOS-N SSSGDDDD)
Q2  value SiRA12BDP  [Power56-8_5x6]  (hidden comment: Transistor MOS-N SSSGDDDD)
Q14  value 2N7002-7-F  [SOT-23-3]  (hidden comment: Transistor MOS-N GSD)
Q15  value MMBT3904  [SOT-23-3]  (hidden comment: Transistor NPN BEC)
Q16  value BSC060P03NS3E G  [PG-TDSON-8_4.7x6.5]  (hidden comment: Transistor MOS-P SSSGDDDD)
R32  20R  [RES_C_0603]
R33  value 10k  [RES_C_0603]  (hidden comment: Resistor)
R34  value 10k  [RES_C_0603]  (hidden comment: Resistor)
R35  value 0R  Populated: DNP  [RES_C_0603]  (hidden comment: Resistor)
R37  value 470k  [RES_C_0603]  (hidden comment: Resistor)
R38  value 2.2k  [RES_C_0603]  (hidden comment: Resistor)
R39  value 20k  [RES_C_0603]  (hidden comment: Resistor)
R40  value 0R  [RES_C_0603]  (hidden comment: Resistor)
R41  value 10k  [RES_C_0603]  (hidden comment: Resistor)
R42  value 10k  [RES_C_0603]  (hidden comment: Resistor)
R43  value 0R  [RES_C_0603]  (hidden comment: Resistor)
R45  value 10k  [RES_C_0603]  (hidden comment: Resistor)
R46  value 2.2k  [RES_C_0603]  (hidden comment: Resistor)
R47  value 8.2k  [RES_C_0603]  (hidden comment: Resistor)
R48  value 20k  [RES_C_0603]  (hidden comment: Resistor)
R53  value 100k  [RES_C_0603]  (hidden comment: Resistor)
R55  value 750R  [RES_C_0603]  (hidden comment: Resistor)
R101  value 2.55k  [RES_C_0603]  (hidden comment: Resistor)
R102  value 330R  [RES_C_0603]  (hidden comment: Resistor)
R103  value 0R  [RES_C_0603]  (hidden comment: Resistor)
R104  value 20R  [RES_C_0603]  (hidden comment: Resistor)
R105  value 1k  [RES_C_0603]  (hidden comment: Resistor)
R106  value 10k  [RES_C_0603]  (hidden comment: Resistor)
R109  value 86.6k  [RES_C_0603]  (hidden comment: Resistor)
R110  value 12k  [RES_C_0603]  (hidden comment: Resistor)
R111  value 10k  [RES_C_0603]  (hidden comment: Resistor)
R112  value 10k  [RES_C_0603]  (hidden comment: Resistor)
R116  value 500R  [RES_C_0603]  (hidden comment: Resistor)
R119  value 12k  [RES_C_0603]  (hidden comment: Resistor)
R122  value 10k  [RES_C_0603]  (hidden comment: Resistor)
SW1  Manufacturer Part Number: JS202011SCQN  [SW_SLIDE_SMD_JS202011SCQN]  (hidden comment: Switch 6 Pin DPDT)
TP1  Test Point  [CON_TP_TH_V_RED_KEC_5000]  (value not drawn)
TP2  Test Point  [CON_TP_TH_V_BLK_KEC_5001]  (value not drawn)
TP3  Test Point  [CON_TP_TH_V_ORN_KEC_5003]  (value not drawn)
TP5  Test Point  [CON_TP_TH_V_YEL_KEC_5004]  (value not drawn)
TP6  value Black  [CON_TP_TH_V_BLK_KEC_5001]  (hidden comment: Test Point)
TP7  Test Point  [CON_TP_TH_V_RED_KEC_5000]  (value not drawn)
TP8  value Black  [CON_TP_TH_V_BLK_KEC_5001]  (hidden comment: Test Point)
U4  value MCP19035  [DFN-10_3x3]  (hidden comment: MCP19035 DFN-10)
U5  value MCP111/4.6V  [SOT-23-3]  (hidden comment: MCP111_2 SOT-23-3_SC-70-3)
U6  value MIC23201  [MLF-10_3x3_1.6X2.5]  (hidden comment: MIC23201 MLF-10)
U7  value MCP1825/ADJ  [SOT-223-5]  (hidden comment: MCP1825T_ADJE SOT-223)

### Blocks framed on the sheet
Soft Start Circuit: C27 C28 C33 C41-C43 C50 C55 C93 D4 F1 J19 J20 Q14 Q16 R32-R34 R37-R39 R45 R102 R104 SW1 TP1 TP6
12VDC to 5VDC: C29 C37 C39 C40 C44-C49 C51-C54 D3 D5 L1 Q1 Q2 R35 R40-R43 R46-R48 R53 R55 R101 R103 TP7 TP8 U4 U5
5VDC to 3.3VDC: C94-C96 D6 J21 R105 R106 R109 R110 TP2 TP3 U7
5VDC to VCORE: C26 C34-C36 C97-C99 D7 L2 Q15 R111 R112 R116 R119 R122 TP5 U6
Fiducials: FID1-FID6
Mounting Holes: MH1-MH4

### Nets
3V3_BRD: C94.2 D7.1(A) R105.2 R109.2 R122.1 TP3.1 U7.4(VOUT)
5V_BRD: C34.2 C35.2 C36.2 C46.2 C47.2 C48.2 C49.2 C95.2 D5.1(A) L1.2(F) R43.2 R106.1 R111.2 TP7.1 U6.8(SVIN) U6.9(VIN) U7.2(VIN)
DC_IN: C27.2 C28.1 C55.2 F1.1 J20.1 Q16.1(S) Q16.2(S) Q16.3(S) R33.2 R34.2 TP1.1
EARTH_DC: C93.1 J20.0(SHLD) R102.1
FB3V3: R109.1 R110.2 U7.5(ADJ)
FBVCORE: R112.1 R119.2 U6.4(FB)
GND: C26.1 C29.1 C33.1 C34.1 C35.1 C36.1 C37.1 C39.1 C40.1 C41.2 C42.2 C43.1 C44.2 C46.1 C47.1 C48.1 C49.1 C50.1 C53.1 C93.2 C94.1 C95.1 C96.1 C97.1 C98.1 C99.1 D3.1(A) D4.1 D6.2(K) J19.2 J20.2 J21.1(P1) MH1.1 MH2.1 MH3.1 MH4.1 Q2.1(S) Q2.2(S) Q2.3(S) Q14.2(S) R39.1 R45.1 R46.1 R102.2 R103.1 R104.1 R110.1 R116.1 R119.1 TP2.1 TP6.1 TP8.1 U4.11(EP) U5.2(VSS) U6.7(AGND) U6.10(PGND) U6.11(EP) U7.3(GND) U7.6(GND_(TAB))
L5V: C45.2 L1.1(S) Q1.1(S) Q1.2(S) Q1.3(S) Q2.5(D) Q2.6(D) Q2.7(D) Q2.8(D) R35.1 U4.9(PHASE)
LVCORE: L2.1(S) U6.1(SW)
VCORE: C26.2 C97.2 L2.2(F) Q15.1(B) R112.2 TP5.1 U6.3(SNS)
VIN: C27.1 C29.2 C33.2 C37.2 C39.2 C40.2 C41.1 C42.1 C43.2 D4.2 Q1.5(D) Q1.6(D) Q1.7(D) Q1.8(D) Q16.5(D) Q16.6(D) Q16.7(D) Q16.8(D) R32.1 R41.2 U4.4(VIN)
5VL: C53.2 R53.2 U4.6(+VCC)
FB5V: C52.2 C54.1 R47.2 R48.2 R101.2 U4.2(FB)
PG5V: R53.1 U4.5(PWRGD)
NetC28_2: C28.2 R32.2
NetC44_1: C44.1 R35.2
NetC45_1: C45.1 R40.2
NetC50_2: C50.2 Q14.1(G) SW1.2 SW1.5
NetC51_1: C51.1 C52.1 U4.3(COMP)
NetC51_2: C51.2 R47.1
NetC54_2: C54.2 R55.1
NetC55_1: C55.1 R104.2
NetC96_2: C96.2 R106.2 U7.1(~{SHDN})
NetC98_2: C98.2 R111.1 U6.2(EN)
NetC99_2: C99.2 U6.6(SS)
NetD3_2: D3.2(K) R41.1 R42.2 U5.3(VDD)
NetD5_2: D5.2(K) R46.2
NetD6_1: D6.1(A) R105.1
NetD7_2: D7.2(K) Q15.3(C)
NetF1_2: F1.2 J19.1
NetQ1_4: Q1.4(G) U4.10(HDRV)
NetQ2_4: Q2.4(G) U4.7(LDRV)
NetQ14_3: Q14.3(D) R38.1
NetQ15_2: Q15.2(E) R116.2
NetQ16_4: Q16.4(G) R33.1 R38.2
NetR34_1: R34.1 R37.1 R39.2
NetR37_2: R37.2 SW1.1 SW1.4
NetR40_1: R40.1 U4.8(BOOT)
NetR42_1: R42.1 U4.1(~{SHDN}) U5.1(VOUT)
NetR43_1: R43.1 R48.1 R55.2
NetR45_2: R45.2 SW1.3 SW1.6
NetR101_1: R101.1 R103.2
NetR122_2: R122.2 U6.5(PG)

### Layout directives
net class Power: 3V3_BRD, 5V_BRD, 5VL, DC_IN, FB3V3, FBVCORE, GND, L5V, LVCORE, VCORE, VIN

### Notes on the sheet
- Voltage Regulators, GP LEDs, LED Drivers
- (near TP1) DC_IN
- (near TP1) RED
- (near TP8) GND
- 5V @ 15A
- (near SW1) ON
- (near TP7) RED
- (near TP7) 5V
- (near TP6) GND
- OFF
- (near D5) 5V
- (near R48) Rfb1
- Change Rfb2 to change voltage:
- (near R101) Rfb2
- 2.6k = 5.25V
- 2.7k = 5V
- Rfb2 = (0.6 * Rfb1) / (Vout - 0.6)
- 2.55k = 5.30V
- (near U7) 3V3 @ 500mA
- (near TP3) ORANGE
- (near TP3) 3V3
- (near D6) 3V3
- (near TP2) BLACK
- (near TP2) GND
- 1.1V or 1.2V @ 2A
- (near TP5) YELLOW
- (near TP5) 1V1
- (near D7) 1V1
- Terminal Plug
- (near J24) Terminal Plug
- (near J24) Populated at Final Assembly
- Labels drawn without touching a wire or pin: 3V3_BRD, 5V_BRD, FB3V3, FBVCORE, GND, L5V, LVCORE, VCORE

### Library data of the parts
?#6 = Title Block Tabloid
C26 C35 C36 C49 = CAP1337: as C9-C15 on sheet 11115-4-USB-C Downstream 1-2
C27 C94 C95 = CAP0373: Capacitor; Manufacturer 1: Wurth Electronics Inc; Manufacturer Part Number 1: 885012107014; Voltage: 16V; Description_: CAP CER 10uF 16V 10% X5R SMD 0805; Tolerance: 10%; Temperature Coeffcient: X5R; Type: Ceramic; Populated: Yes; Dev Tools Status: Production
C28 C33 C40 C43 C55 C93 = CAP1337: Capacitor; Manufacturer 1: TDK Corporation; Manufacturer Part Number 1: CGA2B3X7R1V104K050BB; Voltage: 35V; Description_: CAP CER 0.1uF 35V 10% X7R SMD 0402; Dev Tools Status: Production; Tolerance: 10%; Temperature Coeffcient: X7R; Type: Ceramic; Owner: Sam Charles; Populated: YES
C29 C37 C39 = CAP1998: Capacitor; Manufacturer 1: WUERTH ELEKTRONIK; Manufacturer Part Number 1: 885012108022; Description_: CAP CER 10uF 50V 10% X5R SMD 1206; Dev Tools Status: Design; Tolerance: 10%; Temperature Coeffcient: X5R; Type: Ceramic; Owner: Cristian Papuc; Populated: YES
C34 C97 = CAP1259: Capacitor; Manufacturer 1: Samsung Electro-Mechanics America, Inc; Manufacturer Part Number 1: CL31B226KPHNNNE; Voltage: 10V; Description_: CAP CER 22uF 10V 10% X7R SMD 1206; Tolerance: 10%; Temperature Coeffcient: X7R; Type: Ceramic; Owner: Bogdan Popescu; Populated: YES
C41 C42 = CAP2007: Capacitor; Manufacturer 1: KEMET; Manufacturer Part Number 1: EDT476M050S9MAA; Description_: CAP ALUM 47uF 50V 20% SMD F; Dev Tools Status: Design; Tolerance: 20%; Type: Aluminum; Owner: Jennifer Hancock; Populated: YES
C44 = CAP2214: Capacitor; Manufacturer 1: TDK Corporation; Manufacturer Part Number 1: CGA3E3X7R1H334K080AB; Voltage: 50V; Description_: CAP CER 0.33uF 50V 20% X7R AEC-Q200 SMD 0603; Dev Tools Status: Design; Tolerance: 10%; Temperature Coeffcient: X7R; Type: Ceramic; Owner: Sam Charles
C45 = CAP2214: Capacitor; Manufacturer 1: TDK Corporation; Manufacturer Part Number 1: CGA3E3X7R1H334K080AB; Voltage: 50V; Description_: CAP CER 0.33uF 50V 20% X7R AEC-Q200 SMD 0603; Dev Tools Status: Design; Tolerance: 10%; Temperature Coeffcient: X7R; Type: Ceramic; Owner: Sam Charles; Populated: Yes
C46-C48 = CAP0598: Capacitor; Manufacturer 1: Taiyo Yuden; Manufacturer Part Number 1: LMK325BJ107MM-T; Voltage: 10V; Description_: CAP CER 100uF 10V 20% X5R SMD 1210; Tolerance: 20%; Temperature Coeffcient: X5R; Type: Ceramic; Populated: Yes
C50 = CAP0638: Capacitor; Manufacturer 1: Taiyo Yuden; Manufacturer Part Number 1: LMK107BJ105KA-T; Description_: CAP CER 1uF 50V 10% X5R SMD 0603; Dev Tools Status: Production; Tolerance: 10%; Temperature Coeffcient: X5R; Type: Ceramic; Populated: Yes
C51 = CAP1232: Capacitor; Manufacturer 1: TDK; Manufacturer Part Number 1: C1608C0G1H392J080AA; Voltage: 50V; Description_: CAP CER 3900pF 50V 5% C0G SMD 0603; Tolerance: 5%; Temperature Coeffcient: C0G; Type: Ceramic; Owner: Tad Ahlvers; Populated: YES
C52 = CAP0088: Capacitor; Manufacturer 1: KEMET; Manufacturer Part Number 1: C0603C330J5GACTU; Voltage: 50V; Description_: CAP CER 33pF 50V 5% NP0 SMD 0603; Dev Tools Status: Production; Tolerance: 5%; Temperature Coeffcient: NP0; Type: Ceramic; Populated: Yes
C53 = CAP1288: Capacitor; Manufacturer 1: TDK Corporation; Manufacturer Part Number 1: C1608X5R1C475K080AC; Voltage: 16V; Description_: CAP CER 4.7uF 16V 10% X5R SMD 0603; Tolerance: 10%; Temperature Coeffcient: X5R; Type: Ceramic; Owner: Jairuz Agang-ang; Populated: Yes
C54 = CAP0413: Capacitor; Manufacturer 1: Panasonic; Manufacturer Part Number 1: ECJ-1VC1H681J; Voltage: 50V; Description_: CAP CER 680pF 50V 5% NP0 SMD 0603; Tolerance: 5%; Temperature Coeffcient: NP0; Type: Ceramic; Populated: Yes
C96 = CAP1337: as C71 on sheet 11115-4-USB-C Downstream 1-2
C98 = CAP1208: Capacitor; Manufacturer 1: Murata; Manufacturer Part Number 1: GRM155R61A225KE95D; Voltage: 10V; Description_: CAP CER 2.2uF 10V 10% X5R 0402; Tolerance: 10%; Temperature Coeffcient: X5R; Type: Ceramic; Owner: Tad Ahlvers; Populated: YES
C99 = CAP0603: Capacitor; Manufacturer 1: AVX; Manufacturer Part Number 1: 06033A471JAT2A; Voltage: 25V; Description_: CAP CER 470pF 25V 5% NP0 SMD 0603; Tolerance: 5%; Temperature Coeffcient: NP0; Type: Ceramic; Populated: Yes
D3 = DIODE1204: Manufacturer 1: ON Semiconductor; Description_: DIODE ZENER 5.1V 200MW SOD323; Dev Tools Status: Production; Type: Zener Single; Power: 200mW; Owner: Tim Moffat; Populated: YES
D4 = DIODE1259: Manufacturer 1: STMicroelectronics                                                                               STMicroelectronics; Manufacturer Part Number 1: SMA6T18AY; Value: 15.3VWM 32.3VC; Description_: TVS DIODE 15.3VWM 32.3VC SMA; Dev Tools Status: Design; Power: 600W; Reverse Voltage: 15.3V; Owner: Jose Garcia; Populated: YES
D5-D7 = DIODE1155: as D1 on sheet 11115-5-USB-A Downstream 3-4
F1 = FUSE1018: Manufacturer 1: Littelfuse Inc.; Manufacturer Part Number 1: 0154010.DR; Description_: RES FUSE 10A 125VAC/VDC FAST SMD 2-SMD; Dev Tools Status: Design; Voltage: 125V; Owner: Sam Charles; Populated: YES
J19 = CON1738: Manufacturer 1: On Shore Technology Inc.; Manufacturer Part Number 1: OSTOQ025451; Value: TERMINAL 1X2; Description_: CON TERMINAL 5.08mm 1X2 Male 20A TH RA; Dev Tools Status: Design; Owner: Sam Charles; Voltage: 300V; Current: 20A; Populated: YES
J20 = CON1784: Manufacturer 1: CUI Inc.; Manufacturer Part Number 1: PJ-063BH; Description_: CON POWER 2.5mm 5.5mm TH R/A; Dev Tools Status: Design; Owner: Sam Charles; Voltage: 24V; Current: 8A; Populated: YES
J21 = CON1102: CON HDR-2.54 Male 1x1 Gold 5.97MH TH VERT; Manufacturer 1: TE Connectivity; Manufacturer Part Number 1: 5-146280-1; Description_: CON HDR-2.54 Male 1x1 Gold 5.84MH TH VERT; Dev Tools Status: Production; Owner: Bogdan P (M91398)
J24 = MECH0287: Manufacturer 1: On Shore Technology Inc.; Description_: MECH HW CON TERM BLOCK 1X2 MALE; Dev Tools Status: Design; Owner: Sam Charles; Populated: YES
L1 = IND1556: Manufacturer 1: Wurth Electronics Inc.; Manufacturer Part Number 1: 7443551200; Description_: INDUCTOR 2uH 23A 20% SMD L12.8W12.8H6.2; Dev Tools Status: Design; Owner: Sam Charles; Saturation Current: 22A; Test Frequency: 100kHz; Populated: YES
L2 = IND1560: Manufacturer 1: Murata Electronics North America; Manufacturer Part Number 1: LQH5BPN1R5NT0L; Description_: INDUCTOR 1.5uH 3A 20% SMD L5W5H2.2; Dev Tools Status: Design; Owner: Sam Charles; DCR: 0.028R; Saturation Current: 5A; RMS Current: 3A; Test Frequency: 100kHz; Populated: YES
LABEL1 = 08-00028: Description_: LABEL, ASSY W/REV LEVEL (SMALL MODULES) PER MTS-0002; Dev Tools Status: Production; Populated: MECH
PAD1 = MECH0087: Manufacturer 1: 3M; Manufacturer Part Number 1: SJ5076BLACK; Description_: MECH HW RUBBER PAD Cylindrical flat top D8H2.8 Black; Dev Tools Status: Production; Owner: Bogdan Popescu; Populated: MECH
PAD2-PAD4 = MECH0087: Manufacturer 1: 3M; Manufacturer Part Number 1: SJ5076BLACK; Value: RUBBER PAD D8H2.8; Description_: MECH HW RUBBER PAD Cylindrical flat top D8H2.8 Black; Dev Tools Status: Production; Owner: Bogdan Popescu; Populated: MECH
Q1 = TRA1333: Manufacturer 1: Vishay / Siliconix; Manufacturer Part Number 1: SIRA24DP-T1-GE3; Description_: TRANS FET N-CH SiRA24DP-T1-GE3 25V 60A 62.5W PPAK SO-8; Dev Tools Status: Production; Type: FET; Current: 60A; Drain to Source Voltage: 25V; Gate to Source Voltage: +20V/-16V; Power: 62.5W; Owner: Cristian Papuc; Populated: YES
Q2 = TRA1334: Manufacturer 1: Vishay Siliconix; Manufacturer Part Number 1: SIRA12BDP-T1-GE3; Description_: TRANS FET N-CH SiRA12BDP-T1-GE3 30V 60A 38W PPAK SO-8; Dev Tools Status: Production; Type: FET; Current: 60A; Drain to Source Voltage: 30V; Gate to Source Voltage: +20V/-16V; Power: 38W; Owner: Cristian Papuc; Populated: YES
Q14 = TRA1102: as Q7 on sheet 11115-4-USB-C Downstream 1-2
Q15 = TRA0006: Transistor Bipolar; Manufacturer 1: Diodes Incorporated; Manufacturer Part Number 1: MMBT3904-7; Description_: TRANS BJT NPN MMBT3904 40V 200mA 310mW SOT-23-3; Dev Tools Status: Production; Type: BJT; Current: 200mA; Power: 310mW; Voltage: 40V; Populated: Yes
Q16 = TRA1208: Transistor MOS; Manufacturer 1: Infineon Technologies; Manufacturer Part Number 1: BSC060P03NS3EGATMA1; Description_: TRANS FET P-CH BSC060P03NS3E G -30V -100A 83W PG-TDSON-8; Dev Tools Status: Design; Type: FET; Current: 17.7A; Drain to Source Voltage: -30V; Gate to Source Voltage: 25V; Power: 83W; Owner: Iulian Margarit; Populated: YES
R32 = RES1137: Resistor; Manufacturer 1: Panasonic; Manufacturer Part Number 1: ERJ-3EKF20R0V; Tolerance: 1%; Description_: RES TKF 20R 1% 1/10W SMD 0603; Voltage: 75V; Temperature Coeffcient: 100ppm/C; Power: 1/10W; Owner: Bogdan P (M91398); Populated: Yes
R33 R34 R41 R42 R45 R106 R111 R112 R122 = RSMT0625: as R5 on sheet 11115-4-USB-C Downstream 1-2
R35 = RSMT0001: Manufacturer 1: Panasonic; Manufacturer Part Number 1: ERJ-3GSY0R00V; Description_: RES TKF 0R 1/10W SMD 0603; Dev Tools Status: Production; Power: 1/10W
R37 = RES1185: Manufacturer 1: Vishay; Manufacturer Part Number 1: CRCW0603470KFKEA; Tolerance: 1%; Description_: RES TKF 470k 1% 1/10W SMD 0603; Dev Tools Status: Production; Voltage: 75V; Temperature Coeffcient: 100ppm/C; Power: 1/10W; Owner: Mihai T (M91442); Populated: Yes
R38 = RES1130: Manufacturer 1: Panasonic; Manufacturer Part Number 1: ERJ-3EKF2201V; Tolerance: 1%; Description_: RES TKF 2.2k 1% 1/10W SMD 0603; Dev Tools Status: Production; Voltage: 75V; Temperature Coeffcient: 100ppm/C; Power: 1/10W; Owner: Bogdan P (M91398); Populated: Yes
R39 = RSMT0309: Manufacturer 1: Panasonic; Manufacturer Part Number 1: ERJ-3EKF2002V; Tolerance: 1%; Description_: RES TKF 20k 1% 1/10W SMD 0603; Dev Tools Status: Production; Voltage: 50V; Temperature Coeffcient: 100ppm/C; Power: 1/10W; Populated: Yes
R40 R43 R103 = RSMT0001: Manufacturer 1: NIC Components; Manufacturer Part Number 1: NRC06Z0TRF; Description_: RES TKF 0R 1/10W SMD 0603; Power: 1/10W; Populated: Yes
R46 = RES1130: as R3 on sheet 11115-5-USB-A Downstream 3-4
R47 = RES1210: Manufacturer 1: Panasonic; Manufacturer Part Number 1: ERJ-3EKF8201V; Tolerance: 1%; Description_: RES TKF 8.2k 1% 1/10W SMD 0603; Voltage: 75V; Temperature Coeffcient: 100ppm/C; Power: 1/10W; Owner: Adrian M (M91404); Populated: Yes
R48 = RSMT0309: Manufacturer 1: Yageo; Manufacturer Part Number 1: 9C06031A2002FKHFT; Tolerance: 1%; Description_: RES TKF 20k 1% 1/10W SMD 0603; Voltage: 50V; Temperature Coeffcient: 100ppm/C; Power: 1/10W; Populated: Yes
R53 = RSMT0215: Manufacturer 1: Panasonic; Manufacturer Part Number 1: ERJ-3EKF1003V; Description_: RES TKF 100k 1% 1/10W SMD 0603; Voltage: 75V; Temperature Coeffcient: 100ppm/C; Power: 1/10W; Populated: Yes; Tolerance: 1%; Dev Tools Status: Production
R55 = RES1052: Manufacturer 1: Vishay; Manufacturer Part Number 1: CRCW0603750RFKEA; Tolerance: 1%; Description_: RES TKF 750R 1% 1/10W SMD 0603; Voltage: 75V; Temperature Coeffcient: 100ppm/C; Power: 1/10W; Owner: Tad Ahlvers; Populated: YES
R101 = RES1707: Manufacturer 1: Yageo; Manufacturer Part Number 1: RC0603FR-072K55L; Tolerance: 1%; Description_: RES TKF 2.55k 1% 1/10W SMD 0603; Dev Tools Status: Production; Temperature Coeffcient: 100ppm/C; Power: 1/10W; Owner: Razvan Cristescu; Populated: YES
R102 = RSMT0626: Manufacturer 1: Panasonic; Manufacturer Part Number 1: ERJ-3EKF3300V; Tolerance: 1%; Description_: RES TKF 330R 1% 1/10W SMD 0603; Voltage: 75V; Temperature Coeffcient: 100ppm/C; Power: 1/10W; Populated: Yes
R104 = RES1137: Manufacturer 1: Panasonic; Manufacturer Part Number 1: ERJ-3EKF20R0V; Tolerance: 1%; Description_: RES TKF 20R 1% 1/10W SMD 0603; Voltage: 75V; Temperature Coeffcient: 100ppm/C; Power: 1/10W; Owner: Bogdan P (M91398); Populated: Yes
R105 = RSMT0138: Manufacturer 1: Panasonic; Manufacturer Part Number 1: ERJ-3EKF1001V; Tolerance: 1%; Description_: RES TKF 1k 1% 1/10W SMD 0603; Voltage: 75V; Temperature Coeffcient: 100ppm/C; Power: 1/10W; Populated: Yes; Dev Tools Status: Production
R109 = RES1540: Manufacturer 1: Panasonic Electronic Components; Manufacturer Part Number 1: ERJ-3EKF8662V; Tolerance: 1%; Description_: RES TKF 86.6k 1% 1/10W SMD 0603; Dev Tools Status: Design; Temperature Coeffcient: ±100ppm/°C; Power: 1/10W; Owner: Sam Charles; Populated: YES
R110 R119 = RES1120: Manufacturer 1: Yageo; Manufacturer Part Number 1: RC0603FR-0712KL; Tolerance: 1%; Description_: RES TKF 12k 1% 1/10W SMD 0603; Voltage: 50V; Temperature Coeffcient: 100ppm/C; Power: 1/10W; Owner: Mihai T (M91442); Populated: Yes; Dev Tools Status: Production
R116 = RSMT0590: Manufacturer 1: Stackpole Electronics Inc; Manufacturer Part Number 1: RMC 1/16 500 5% R; Tolerance: 5%; Description_: RES TKF 500R 5% 1/10W SMD 0603; Dev Tools Status: Production; Voltage: 50V; Temperature Coeffcient: 100ppm/C; Power: 1/10W; Populated: Yes
SW1 = SWITCH1002: SWITCH SLIDE DPDT 6VDC 0.3A SMT; Manufacturer: C&K Components; Manufacturer 1: C&K; Value: JS202011SCQN; Switch Function: OFF-On; Contact Rating @ Voltage: 0.3A @ 6VDC; Actuator Type: Standard; Description_: SWITCH SLIDE DPDT 6V 300mA JS202011SCQN SMD; Dev Tools Status: Production; Owner: Leah Whitaker; Voltage: 6V; Current: 300mA; Populated: YES
TP1 = MISC0027: Manufacturer 1: Keystone; Manufacturer Part Number 1: 5000; Value: Red; Description_: MISC, TEST POINT MULTI PURPOSE MINI RED; Dev Tools Status: Production; Owner: Stephen Humberd; Populated: YES
TP2 = MISC0026: Manufacturer 1: Keystone; Manufacturer Part Number 1: 5001; Value: TP LOOP Black; Description_: MISC, TEST POINT MULTI PURPOSE MINI BLACK; Dev Tools Status: Production; Owner: Stephen Humberd; Populated: YES
TP3 = CON1282: Manufacturer 1: Keystone Electronics; Manufacturer Part Number 1: 5003; Value: TP LOOP Orange; Description_: CON TP LOOP Orange TH; Dev Tools Status: Design; Owner: Stephen Humberd; Populated: YES
TP5 = MISC0119: Manufacturer 1: Keystone; Manufacturer Part Number 1: 5004; Value: TP LOOP Yellow; Description_: MISC, TEST POINT PC MINI, 0.040" D YELLOW; Dev Tools Status: Production; Owner: Stephen Humberd; Populated: YES
TP6 TP8 = MISC0026: Manufacturer 1: Keystone; Manufacturer Part Number 1: 5001; Description_: MISC, TEST POINT MULTI PURPOSE MINI BLACK; Dev Tools Status: Production; Owner: Stephen Humberd; Populated: YES
TP7 = MISC0027: Manufacturer 1: Keystone; Manufacturer Part Number 1: 5000; Value: TP LOOP Red; Description_: MISC, TEST POINT MULTI PURPOSE MINI RED; Dev Tools Status: Production; Owner: Stephen Humberd; Populated: YES
U4 = MIC5997: Manufacturer 1: Microchip; Manufacturer Part Number 1: MCP19035-BAABE/MF; Description_: MCHP ANALOG PWM CONTROLLER 600kHz MCP19035-BAABE/MF DFN-10; MAPS Description: Int.osc.600kHz, int.Vref 600mV, Overcurrent Th. 200Mv;Dead T 12ns; Dev Tools Status: Production; Owner: Tad Ahlvers; MPC: PJAA24E2XB00; LeadContent: Pb-FREE; PackingMedia: TUBE; Stage: REL; LeadCount: 10; PackageWidth: 3x3x0.9mm; ForceMinOrderQtyMult: False; MinOrderQty: 0; TempRange: -40C to +125C; tblDeviceFamilyID: 3103; UVLO: Yes; Topology: Sync. Buck; SingleDual: Single; ResetOutput: No; InputVoltageRangeMin: 4.5; InputVoltageRangeMax: 30; QuiescentCurrent: 6; ControlPWM: PWM; SwitchingFrequency: 600
U5 = MIC2289: Manufacturer 1: Microchip Technology; Manufacturer Part Number 1: MCP111T-475E/TT; Description_: MCHP ANALOG VOLTAGE DETECTOR 4.75V MCP111T-475E/TT SOT-23-3; MAPS Description: 1uA Supervisor Push-Pull Active Low; Dev Tools Status: Production; Owner: Sam Charles; MPC: A7BJ5YC6X475; LeadContent: Pb-FREE; PackingMedia: T/R; Stage: REL; LeadCount: 3; PackageWidth: 1.3mm; ForceMinOrderQtyMult: True; MinOrderQty: 1; TempRange: -40C to +125C; tblDeviceFamilyID: 1178; VccRangeMax: 5.5; NominalResetVoltage: 1.87, 2.29, 2.59, 2.86, 2.87, 3.03, 4.31, 4.56; SuperOutput: Open-Drain; Populated: YES
U6 = MIC7256: Manufacturer 1: Microchip Technology; Manufacturer Part Number 1: MIC23201YML-TR; Description_: MCHP ANALOG SWITCHER Buck 0.95V to 3.6V 2A MIC23201YML-TR MLF-10; MAPS Description: 2MHz PWM 2A Buck Regulator with HSC; Dev Tools Status: Design; Owner: Sam Charles; MPC: 22830YJFAA02; LeadContent: Pb-FREE; PackingMedia: T/R; Stage: REL; LeadCount: 10; PackageWidth: 3x3x0.9mm; ForceMinOrderQtyMult: True; MinOrderQty: 5000; TempRange: -40C to +125C; tblDeviceFamilyID: 7698; InputVoltageRangeMin: 2.7; InputVoltageRangeMax: 5.5; VoutMin: 0.62; VoutMax: 3.6; QuiescentCurrent: 1.15; SwitchingFrequency: 2000; Populated: YES
U7 = MIC7428: Manufacturer 1: Microchip; Manufacturer Part Number 1: MCP1825T-ADJE/DC; Description_: MCHP ANALOG LDO ADJ MCP1825T-ADJE/DC SOT-223-5; Dev Tools Status: Design; Owner: Sam Charles; Populated: YES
